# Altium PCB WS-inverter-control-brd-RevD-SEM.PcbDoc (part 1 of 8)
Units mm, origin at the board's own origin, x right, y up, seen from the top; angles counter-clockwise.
Board outline 270 x 105.92 mm, 6 copper layers (Top Layer, Int1 (Sign), Int2 (PWR), Int3 (GND), Int4 (Sign), Bottom Layer), stack 1.509 mm thick; 709 components, 375 nets, 2377 pads, 1332 vias.
Unrouted connection lines stored in the file: 55.
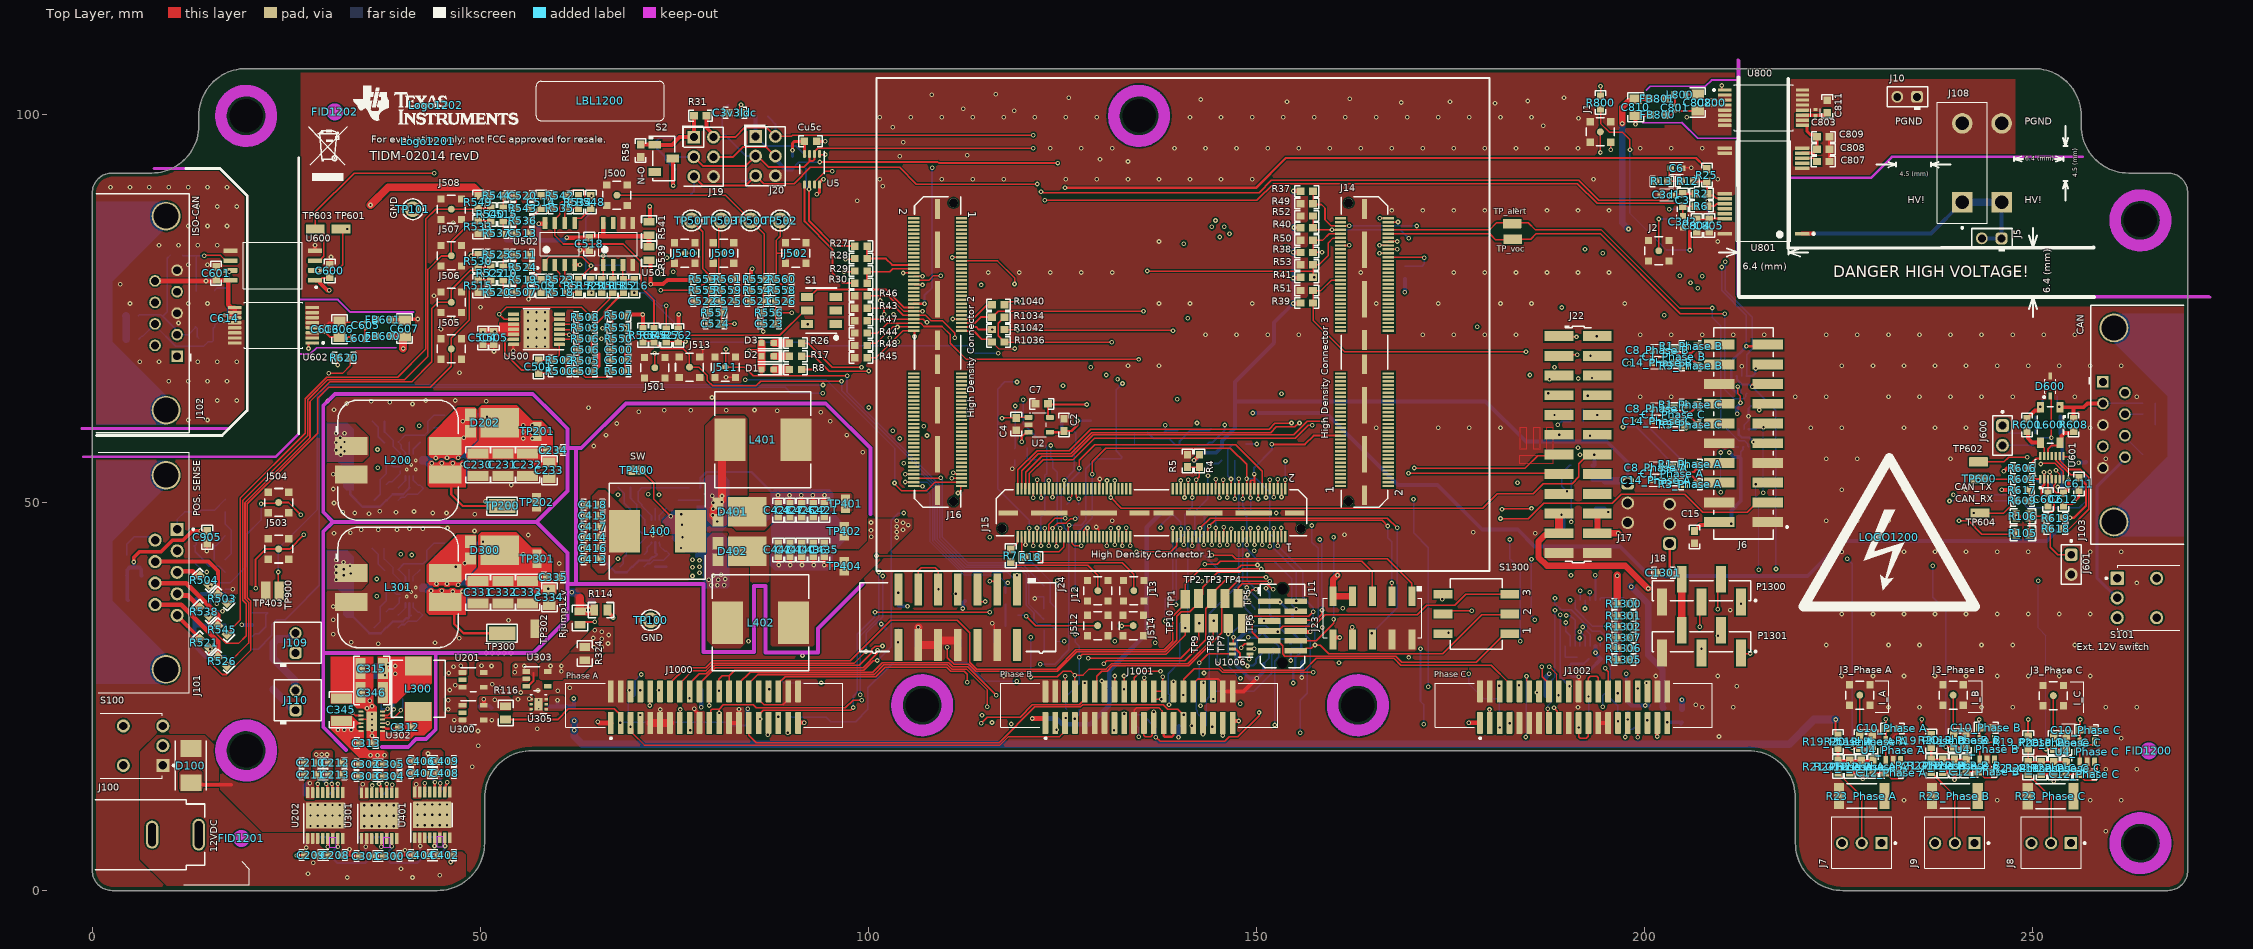
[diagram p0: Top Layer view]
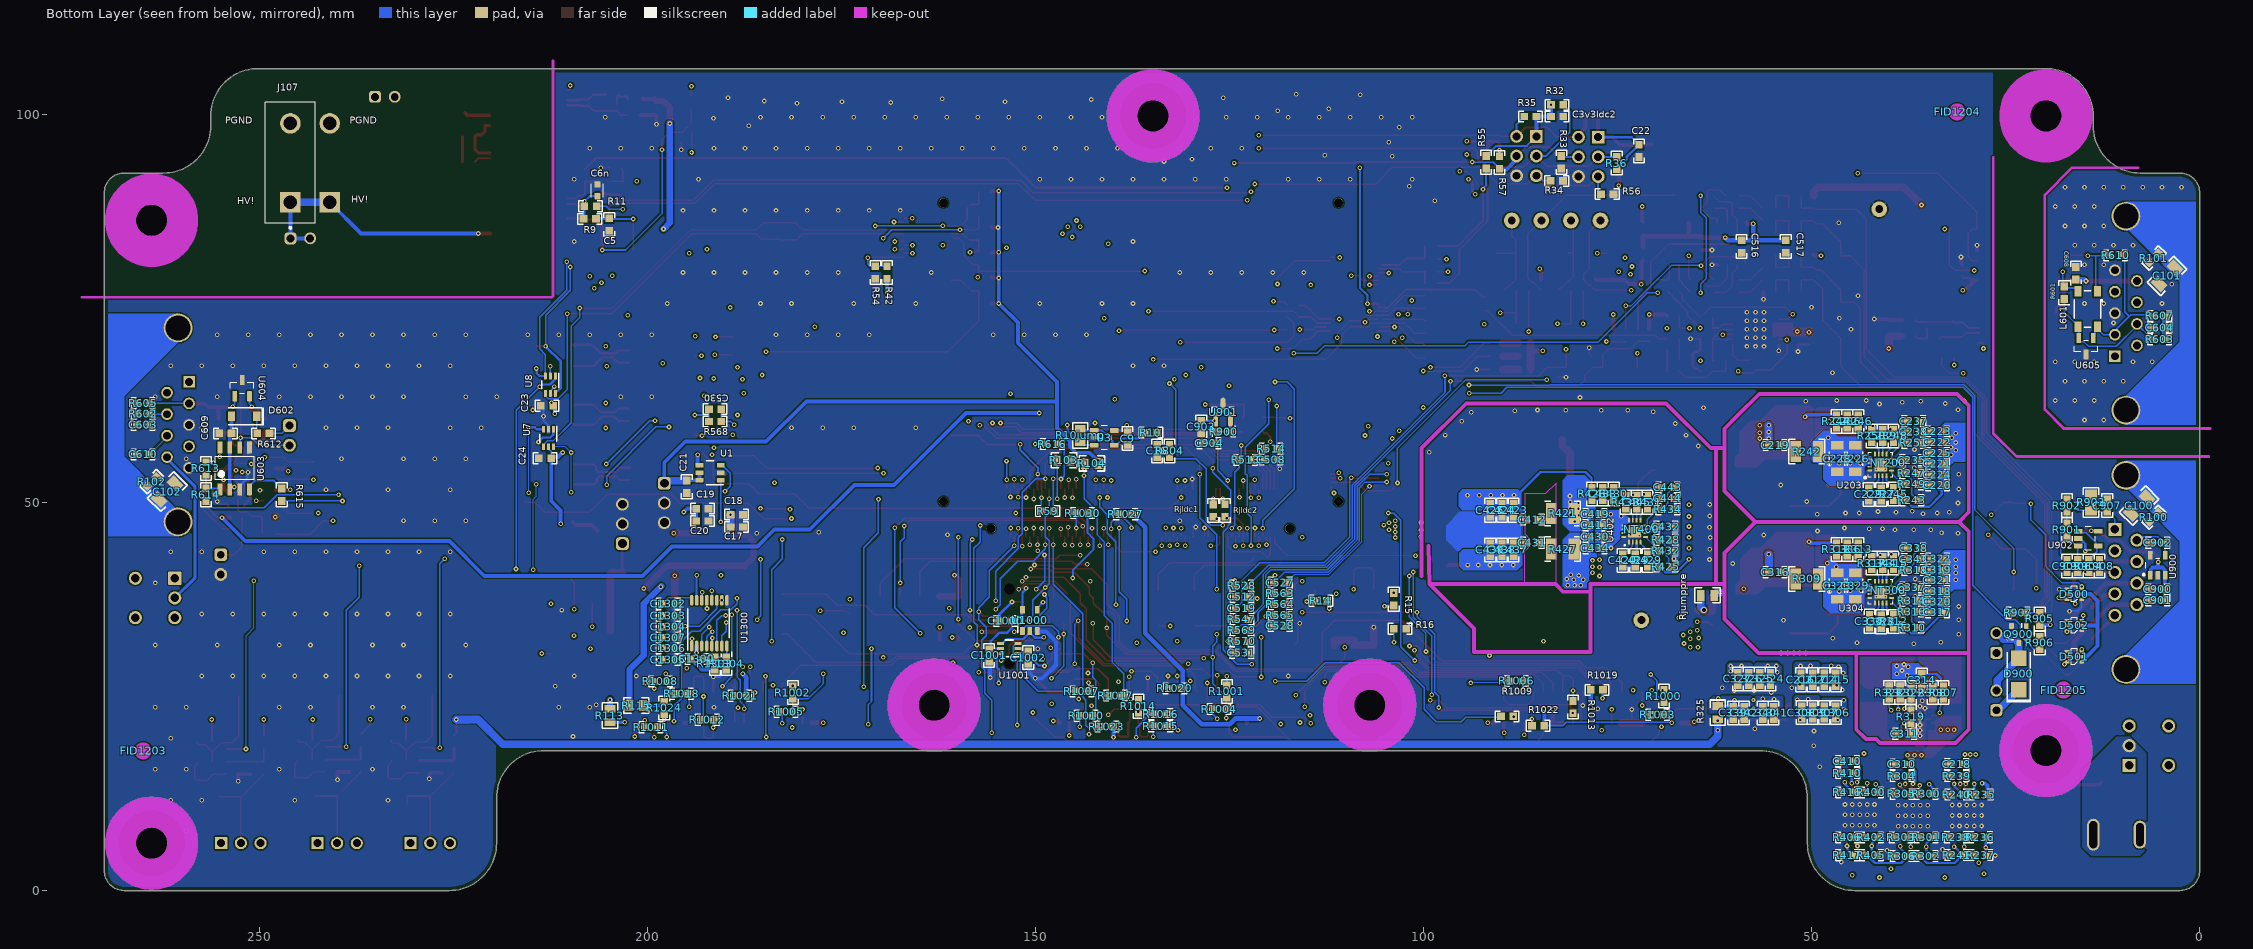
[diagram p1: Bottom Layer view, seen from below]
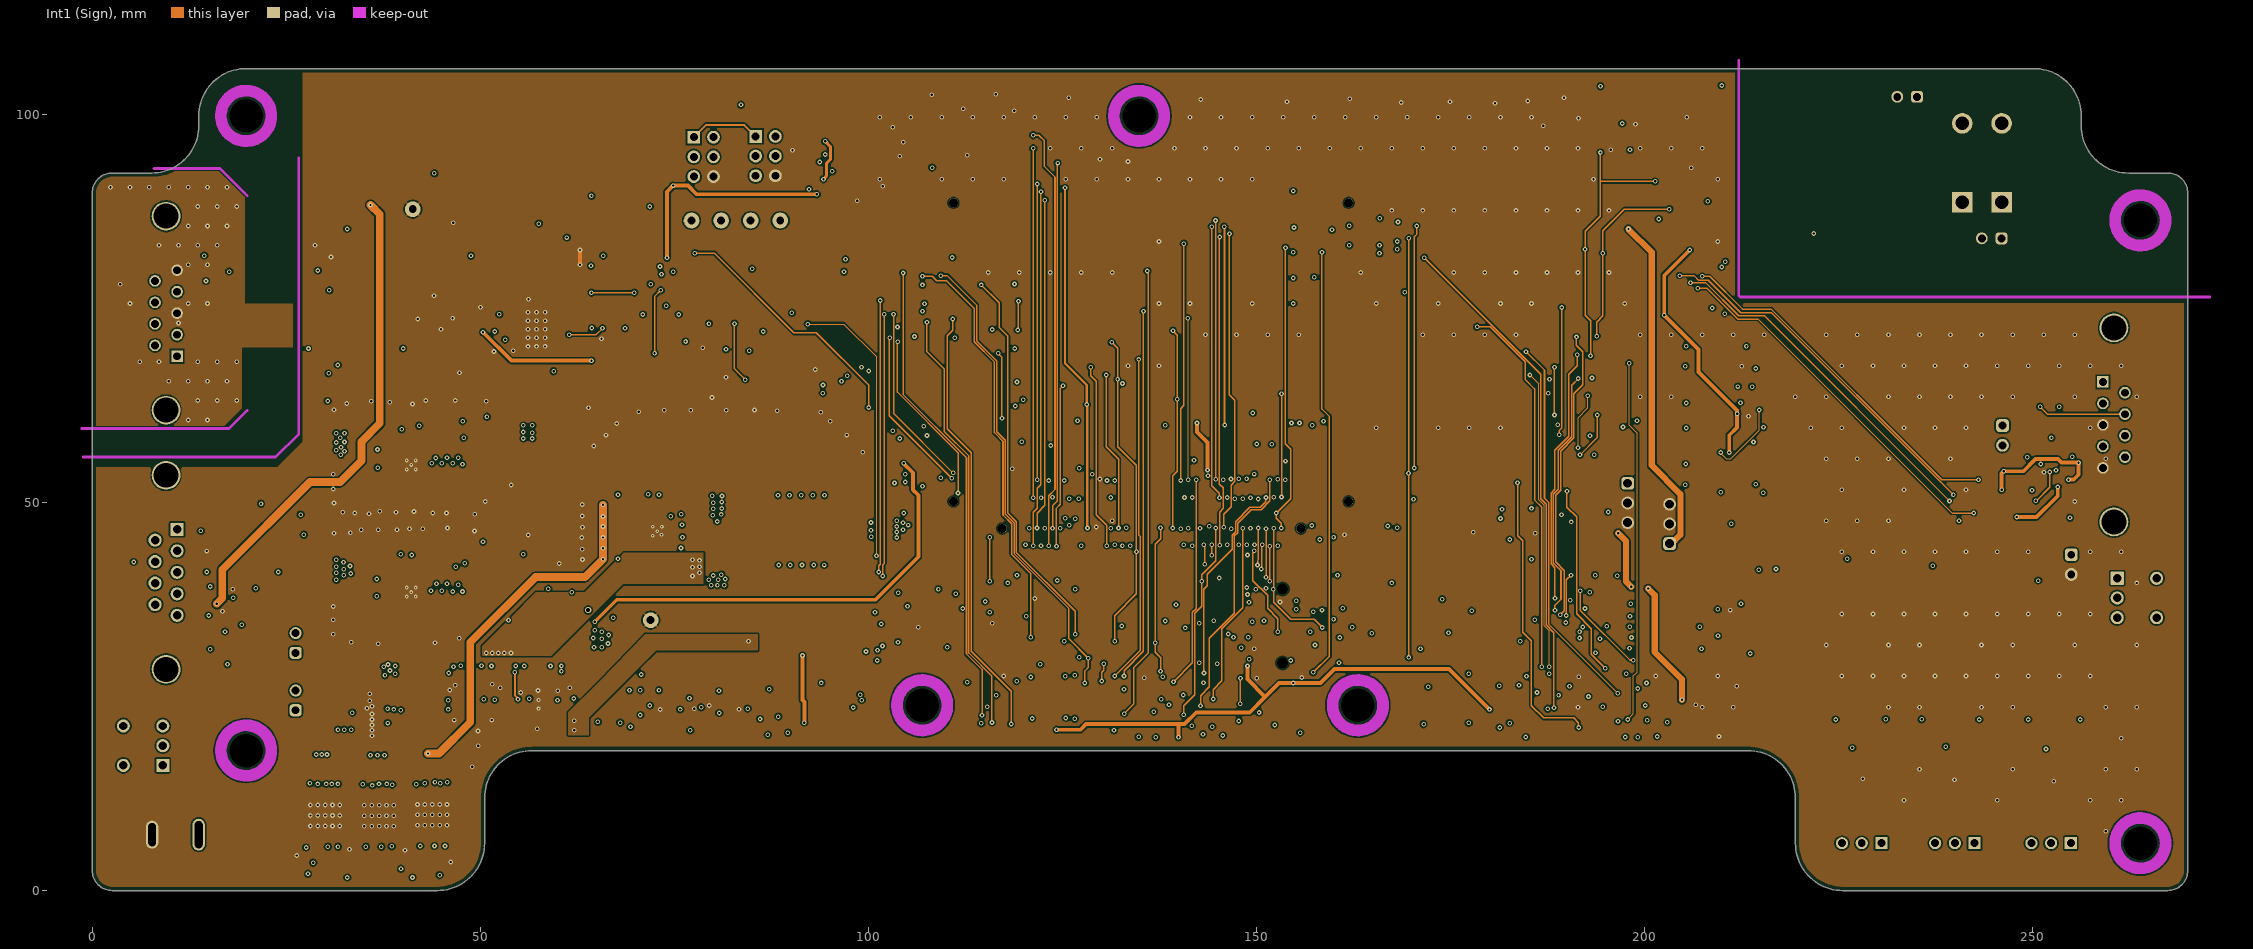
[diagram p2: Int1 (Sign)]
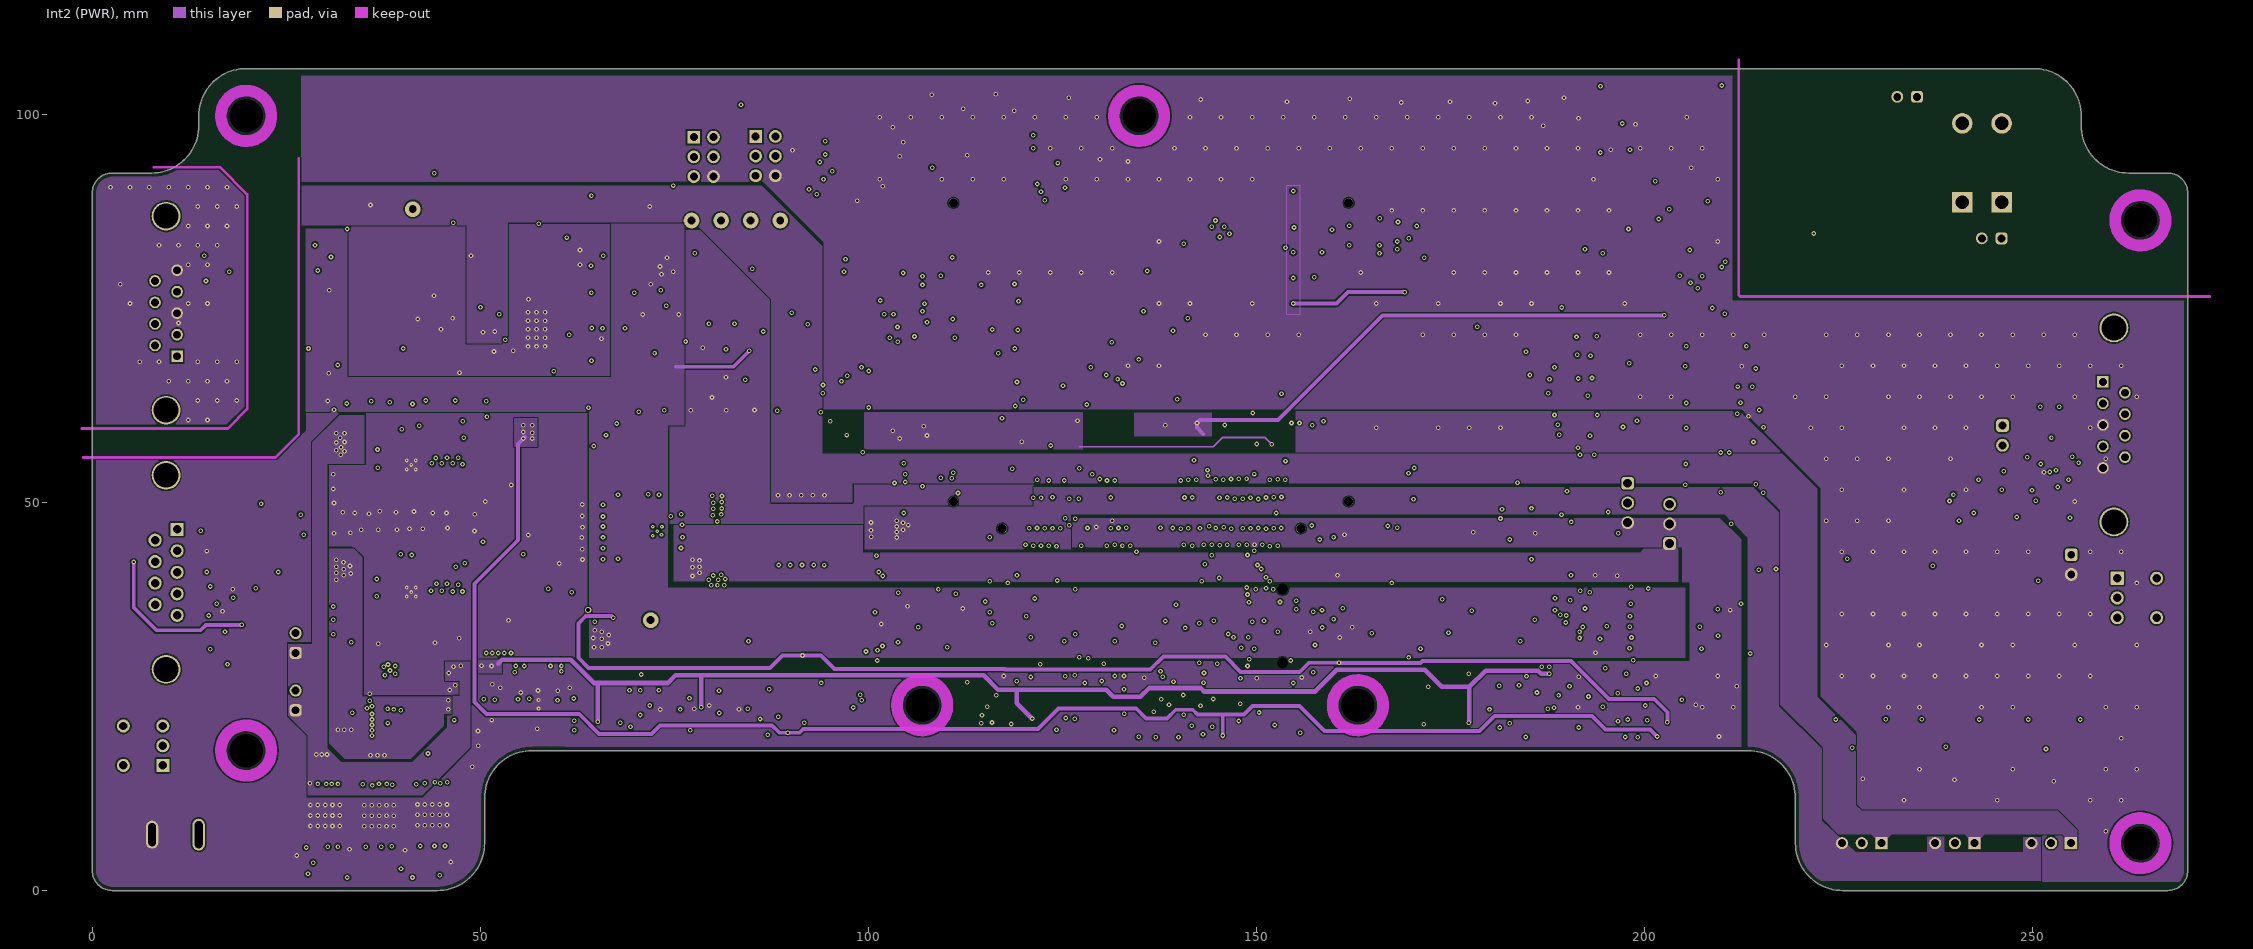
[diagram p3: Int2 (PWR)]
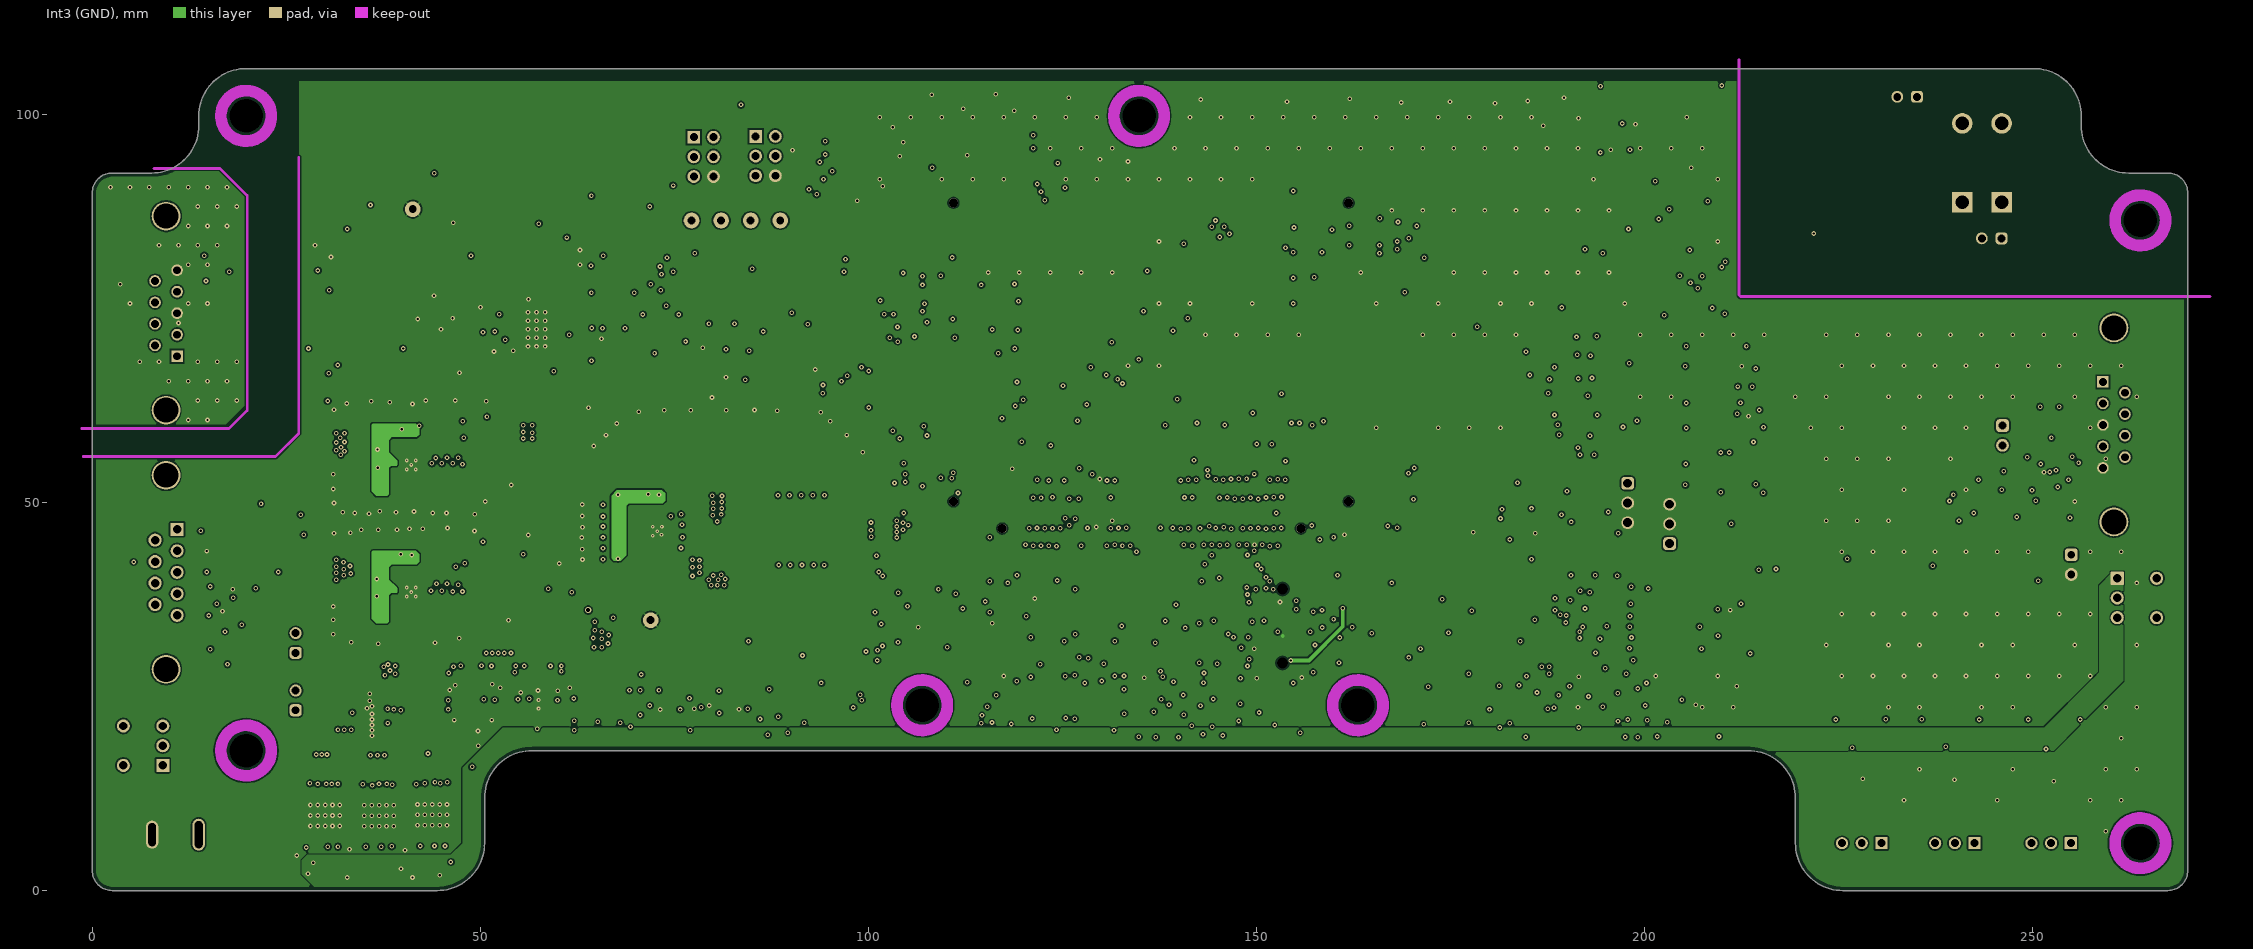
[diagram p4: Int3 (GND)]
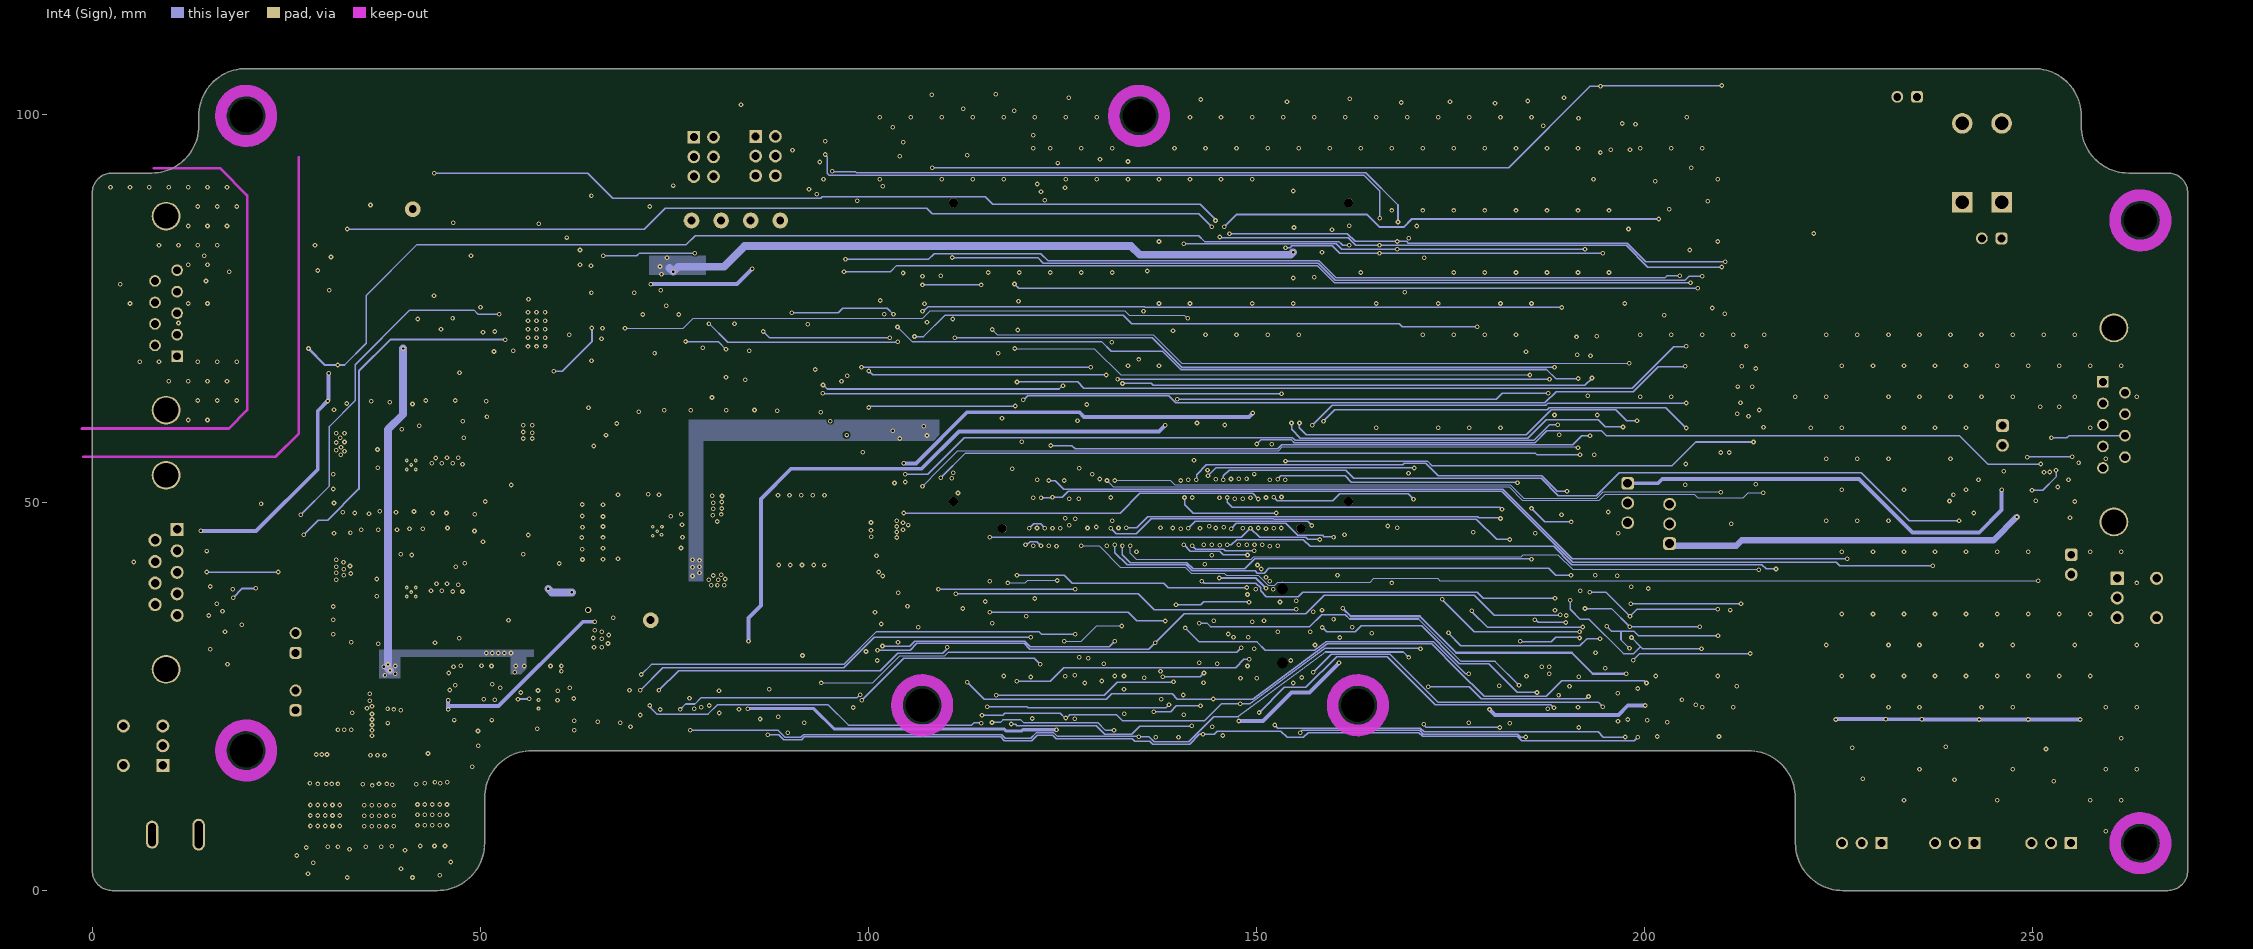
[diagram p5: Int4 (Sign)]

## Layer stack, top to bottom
Top Solder: solder mask 0.0254, SM-001, Dk 4
Top Layer: signal copper 0.035
Dielectric 1: prepreg 0.1118, Composite dielectric, Dk 4.1
Dielectric 2: prepreg 0.0787, Composite dielectric, Dk 4.1
Int1 (Sign): signal copper 0.018
Dielectric 3: core 0.4064, Core-034, Dk 4.6
Int2 (PWR): signal copper 0.018
Dielectric 4: prepreg 0.0864, PP-010, Dk 4
Dielectric 5: prepreg 0.0864, PP-010, Dk 4
Int3 (GND): signal copper 0.018
Dielectric 6: core 0.4064, Core-034, Dk 4.6
Int4 (Sign): signal copper 0.018
Dielectric 7: prepreg 0.0787, Composite dielectric, Dk 4.3
Dielectric 8: prepreg 0.1118, Composite dielectric, Dk 4.3
Bottom Layer: signal copper 0.035
Bottom Solder: solder mask 0.0254, SM-001, Dk 4

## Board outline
2.54,0 44.45,0 ccw(c44.45,6.096) 50.546,6.096 50.546,11.938 cw(c56.642,11.938) 56.642,18.034 213.36,18.034 cw(c213.36,11.938) 219.456,11.938 219.456,6.096 ccw(c225.552,6.096) 225.552,0 267.462,0 ccw(c267.462,2.54) 270.002,2.54 270.002,89.916 ccw(c267.462,89.916) 267.462,92.456 262.382,92.456 cw(c262.382,98.552) 256.286,98.552 256.286,99.822 ccw(c250.19,99.822) 250.19,105.918 19.812,105.918 ccw(c19.812,99.822) 13.716,99.822 13.716,98.552 cw(c7.62,98.552) 7.62,92.456 2.54,92.456 ccw(c2.54,89.916) 0,89.916 0,2.54 ccw(c2.54,2.54)

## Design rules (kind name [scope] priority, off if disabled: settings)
AcuteAngle [All] p1: minimum=4.50000000000000E+0001 checktracksonly=FALSE
AssemblyTestPointUsage [All] p1: valid=2
BoardOutlineClearance BoardOutlineClearance_MountingHoles [(ObjectKind = 'Pad') And (Component = 'Free') And (PadIsPlated = 'False')] p1: gap=0.3 ignorepadtopadclearanceinfootprint=FALSE
BoardOutlineClearance BoardOutlineClearance_Poly [OnCopper and IsPoly] p2: gap=0.5 ignorepadtopadclearanceinfootprint=FALSE
BoardOutlineClearance [OnCopper and Not InComponentClass('Logo') and not InComponentClass('FiducialMark') and not InRegion(1000,500,4000,800) and not InPoly] p3: gap=0.3 ignorepadtopadclearanceinfootprint=FALSE
Clearance Clearance_FiducialMark [IsKeepOut vs (ObjectKind = 'Component') And HasParameterValue('ClassName', 'FiducialMark')] p1: gap=0 ignorepadtopadclearanceinfootprint=FALSE
Clearance Clearance_Keepouts [not HasParameterValue('ClassName', 'FiducialMark') vs IsKeepOut] p2: gap=0.2 ignorepadtopadclearanceinfootprint=FALSE
Clearance Clearance_Mounting_Hole [All vs (ObjectKind = 'Pad') And (Component = 'Free') And (PadIsPlated = 'False')] p3: gap=0.3 ignorepadtopadclearanceinfootprint=FALSE
Clearance Clearance_HV [not InNetClass('HVC') vs InNetClass('HVC')] p4: gap=6 ignorepadtopadclearanceinfootprint=TRUE
Clearance Clearance_Poly [InPolygon] p5: gap=0.2 ignorepadtopadclearanceinfootprint=FALSE
Clearance [All] p6: gap=0.1 ignorepadtopadclearanceinfootprint=FALSE
ComponentClearance ComponentClearance_TestPoints [HasFootprint('Keystone5000') or HasFootprint('Keystone5005') vs HasFootprint('Keystone5000') or HasFootprint('Keystone5005')] p1: gap=0.254 collisioncheckmode=3 verticalgap=0.254 showdistances=FALSE
ComponentClearance ComponentClearance_MountingHoles_FiducialMarks [InComponentClass('Mounting Holes') vs InComponentClass('FiducialMark')] p2: gap=1.27 collisioncheckmode=3 verticalgap=0.254 showdistances=FALSE
ComponentClearance ComponentClearance_Shunt [InComponentClass('Header') vs InComponentClass('Shunt')] p3: gap=0 collisioncheckmode=3 verticalgap=0 showdistances=FALSE
ComponentClearance ComponentClearance_Logo [InComponentClass('Logo')] p4: gap=1.27 collisioncheckmode=3 verticalgap=0.254 showdistances=FALSE
ComponentClearance ComponentClearance_SmallPassives [HasFootprint('0201*') or HasFootprint('0402*') or HasFootprint('0508') or HasFootprint('0603*') or HasFootprint('0612') or HasFootprint('0805*') or HasFootprint('0815*') or HasFootprint('0830*') or HasFootprint('1206*') or HasFootprint('1210*') or HasFootprint('1808*') or HasFootprint('1812*') or HasFootprint('1825*') or HasFootprint('2010*') or HasFootprint('2220*') or HasFootprint('2225*') or HasFootprint('2512*') or HasFootprint('2728*') or HasFootprint('3518*') vs HasFootprint('0201*') or HasFootprint('0402*') or HasFootprint('0508') or HasFootprint('0603*') or HasFootprint('0612') or HasFootprint('0805*') or HasFootprint('0815*') or HasFootprint('0830*') or HasFootprint('1206*') or HasFootprint('1210*') or HasFootprint('1808*') or HasFootprint('1812*') or HasFootprint('1825*') or HasFootprint('2010*') or HasFootprint('2220*') or HasFootprint('2225*') or HasFootprint('2512*') or HasFootprint('2728*') or HasFootprint('3518*')] p5: gap=0.38 collisioncheckmode=3 verticalgap=0.254 showdistances=FALSE
ComponentClearance ComponentClearance_THtoSMT [IsThruComponent vs IsSMTComponent] p6: gap=1.016 collisioncheckmode=3 verticalgap=0.762 showdistances=FALSE
ComponentClearance ComponentClearance_THtoTH [IsThruComponent vs IsThruComponent] p7: gap=0.762 collisioncheckmode=3 verticalgap=0.762 showdistances=FALSE
ComponentClearance [All] p8: gap=0.762 collisioncheckmode=3 verticalgap=0.254 showdistances=FALSE donotcheckwithout3dbody=TRUE
DiffPairsRouting [All] p1: maxlimit=2.54 minlimit=0.254 mostfreqgap=0.254 toplayer_minwidth=0.18 toplayer_maxwidth=0.381 toplayer_prefwidth=0.18 midlayer1_minwidth=0.18 midlayer1_maxwidth=0.381 midlayer1_prefwidth=0.18 midlayer2_minwidth=0.18 midlayer2_maxwidth=0.381 midlayer2_prefwidth=0.18 midlayer3_minwidth=0.18 midlayer3_maxwidth=0.381 midlayer3_prefwidth=0.18 midlayer4_minwidth=0.18 midlayer4_maxwidth=0.381 midlayer4_prefwidth=0.18 bottomlayer_minwidth=0.18 bottomlayer_maxwidth=0.381 bottomlayer_prefwidth=0.18 maxuncoupledlength=25.4
FabricationTestPointUsage TestPointUsage [All] p1: valid=2 allowmultiple=FALSE
FabricationTestpoint Testpoint [All] p1: side=3 testpointundercomponent=TRUE minsize=1.016 maxsize=2.54 preferedsize=1.524 minholesize=0 maxholesize=1.016 preferedholesize=0.813 testpointgrid=0.025 allowsidetop=TRUE allowsidebottom=TRUE usegrid=TRUE gridtolerance=0
FanoutControl Fanout_LCC [IsLCC] p1: bgadir=Out bgaviamode=Centered fanoutstyle=Auto fanoutdirection=Alternating viagrid=0.025 // Fanout_LCC (Default Rule)
FanoutControl Fanout_BGA [IsBGA] p2: bgadir=Out bgaviamode=Centered fanoutstyle=Auto fanoutdirection=Alternating viagrid=0.025 // Fanout_BGA (Default Rule)
FanoutControl Fanout_Default [All] p4: bgadir=Out bgaviamode=Centered fanoutstyle=Auto fanoutdirection=Alternating viagrid=0.025 // Fanout_Default (Default Rule)
FanoutControl Fanout_Small [(CompPinCount < 5)] p5: bgadir=Out bgaviamode=Centered fanoutstyle=Auto fanoutdirection=OutThenIn viagrid=0.025 // Fanout_Small (Default Rule)
HoleSize [All] p1: absolutevalues=TRUE maxlimit=6.375 minlimit=0.2 maxpercent=80.000 minpercent=20.000
MinimumAnnularRing MinimumAnnularRing_1 [All] p1: minimumring=0.15
MinimumAnnularRing MinimumAnnularRing_ThermalPadVias [IsVia and InAnyComponent] p2: minimumring=0.15
MinimumSolderMaskSliver MinimumSolderMaskSliver_Logo [InComponentClass('Logo') vs InComponentClass('Logo')] p1: minsoldermaskwidth=0.018
MinimumSolderMaskSliver [All] p2: minsoldermaskwidth=0.1
PlaneConnect [All] p1: planeconnectstyle=Relief reliefexpansion=0.254 reliefentries=4 reliefconductorwidth=0.254 reliefairgap=0.254
PolygonConnect Testpoint-GND-thermal [(InComponent('TP100') or InComponent('TP101')) and InNet('GND')] p1: connectstyle=Relief reliefconductorwidth=0.254 reliefentries=4 polygonreliefangle="45 Angle" airgapwidth=0.2
PolygonConnect [All] p2: connectstyle=Direct reliefconductorwidth=0.254 reliefentries=4 polygonreliefangle="90 Angle" airgapwidth=0.2
RoutingVias ThermalPadVias [IsVia and InAnyComponent] p1: holewidth=0.2 width=0.5 viastyle="Through Hole" minholewidth=0.2 minwidth=0.5 maxholewidth=0.33 maxwidth=0.6
RoutingVias [All] p2: holewidth=0.3 width=0.6 viastyle="Through Hole" minholewidth=0.2 minwidth=0.5 maxholewidth=1 maxwidth=1.5
SilkToBoardRegionClearance [Not ((IsComment or IsDesignator) And (Hide <> 'False')) and not InRegion(1000,500,4000,800)] p1:
SilkToSilkClearance SilkToSilkClearance_Pb-FreeLogo [(HasFootprint('Pb-Free_Overlay_Medium') OR HasFootprint('Pb-Free_Overlay_Small')) vs (HasFootprint('Pb-Free_Overlay_Medium') OR HasFootprint('Pb-Free_Overlay_Small'))] p1: silktosilkclearance=0
SilkToSilkClearance [All] p2: silktosilkclearance=0.102
SilkToSolderMaskClearance SilkToComponentPadClearance [(IsPad or IsFill or IsRegion) and InAnycomponent] p1: minsilkscreentomaskgap=0.1 clearancetoexposedcopper=TRUE
SilkToSolderMaskClearance "Silk to Solder Mask Opening" [All] p2: minsilkscreentomaskgap=0.102 clearancetoexposedcopper=FALSE
SolderMaskExpansion [All] p1: expansion=0.05 istentingtop=FALSE
UnRoutedNet [All] p1: checkbadconnections=TRUE
Width [not InPolygon] p1: maxlimit=2.54 minlimit=0.16 preferedwidth=0.18 minimp=50.000000 maximp=50.000000 favimp=50.000000 checkconnectedcopper=TRUE
14 further rules are at their usual default settings.

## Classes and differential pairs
component class "Safety MCU": C17 C18 C19 C20 C21 J5 J10 J22 U1
component class LDC5073: C3v3ldc C3v3ldc2 C22 Cu5c J19 J20 R31 R32 R33 R34 R35 R36 R55 R56 R57 R58 S2 U5
component class controlSOM_Subsystem: C2 C4 C7 D1 D2 D3 J11 J12 J13 J14 J15 J16 J17 J18 J23 J24 R7 R8 R14 R15 R16 R17 R18 R26 R27 R28 R29 R30 R59 Rjldc1 Rjldc2 S1 TP1 TP2 TP3 TP4 TP5 TP6 TP7 TP8 TP9 TP10 U2
channel class current-sense-lem-new: "Phase A" "Phase B" "Phase C"
component class U_Voltage-sense-LVside: C3 C3d1 C3d2 C5 C6 C6n C9 C16 J1 J2 R2 R6 R9 R10 R10jump R11 R12 R13 R25 U3
component class "U_Current Sense Connector": C15 C23 C24 J6 J7 J8 J9 TP_alert TP_voc U7 U8
component class "Safe State Behavior Settings": R4 R5 R37 R38 R39 R40 R41 R42 R43 R44 R45 R46 R47 R48 R49 R50 R51 R52 R53 R54
component class "Phase C": "C1_Phase C" "C8_Phase C" "C10_Phase C" "C11_Phase C" "C12_Phase C" "C13_Phase C" "C14_Phase C" "J3_Phase C" "R1_Phase C" "R3_Phase C" "R19_Phase C" "R20_Phase C" "R21_Phase C" "R22_Phase C" "R23_Phase C" "R24_Phase C" "U4_Phase C"
component class "Phase B": "C1_Phase B" "C8_Phase B" "C10_Phase B" "C11_Phase B" "C12_Phase B" "C13_Phase B" "C14_Phase B" "J3_Phase B" "R1_Phase B" "R3_Phase B" "R19_Phase B" "R20_Phase B" "R21_Phase B" "R22_Phase B" "R23_Phase B" "R24_Phase B" "U4_Phase B"
component class "Phase A": "C1_Phase A" "C8_Phase A" "C10_Phase A" "C11_Phase A" "C12_Phase A" "C13_Phase A" "C14_Phase A" "J3_Phase A" "R1_Phase A" "R3_Phase A" "R19_Phase A" "R20_Phase A" "R21_Phase A" "R22_Phase A" "R23_Phase A" "R24_Phase A" "U4_Phase A"
component class Designator: C1300 C1301 C1302 C1303 C1304 C1305 C1306 C1307 P1300 P1301 R1300 R1301 R1302 R1303 R1304 R1305 R1306 R1307 S1300 U1300
net class HVC: 5V_iso_AMC_9 ADJ_NC_9 HV Pgndin_1 VSNS_9
differential pair IFB_W_1: +IFB_W_1_P -IFB_W_1_N
differential pair IFB_V_1: +IFB_V_1_P -IFB_V_1_N
differential pair IFB_U_1: +IFB_U_1_P -IFB_U_1_N
differential pair V_1: +V_1_P -V_1_N
differential pair U_1: +U_1_P -U_1_N
differential pair VOUT_C: +VOUT_C_P -VOUT_C_N
differential pair VDC: +VDC_P -VDC_N

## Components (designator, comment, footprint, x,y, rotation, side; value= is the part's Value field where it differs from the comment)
"C1_Phase A" "06031C102KAT2A" 0603#1 203.573,53.699 r270 top value=1000pF (schematic designator C1)
"C1_Phase B" "06031C102KAT2A" 0603#1 203.814,68.792 r270 top value=1000pF (schematic designator C1)
"C1_Phase C" "06031C102KAT2A" 0603#1 203.773,61.299 r270 top value=1000pF (schematic designator C1)
C2 "CGA3E2X7R1H104K080AA" 0603#1 125.205,60.002 r90 top value=0.1uF
C3 "06035A251JAT2A" 0603#1 204.95,88.978 r270 top value=0.00025uF
C3d1 "06035C100KAT2A" FP-06035C100KAT2A_0603-MFG 202.843,89.636 r0 top value=10pF
C3d2 "06035C100KAT2A" FP-06035C100KAT2A_0603-MFG 204.95,86.178 r90 top value=10pF
C3v3ldc "CGA3E2X7R1H104K080AA" 0603#1 82.793,100.211 r180 top value=0.1uF
C3v3ldc2 "CGA3E2X7R1H104K080AA" 0603#1 82.793,99.736 r180 bottom value=0.1uF
C4 "CGA3E2X7R1H104K080AA" 0603#1 119.043,60.103 r270 top value=0.1uF
C5 "GCM1885C2A221JA16D" 0603#1 204.95,85.828 r270 bottom value=220pF
C6 "06035C100KAT2A" FP-06035C100KAT2A_0603-MFG 204.15,93.078 r180 top value=10pF
C6n "06035C100KAT2A" FP-06035C100KAT2A_0603-MFG 206.469,90.224 r270 bottom value=10pF
C7 "CGA3E2X7R1H104K080AA" 0603#1 122.343,62.703 r180 top value=0.1uF
"C8_Phase A" "06035C100KAT2A" FP-06035C100KAT2A_0603-MFG 201.514,54.492 r0 top value=10pF (schematic designator C8)
"C8_Phase B" "06035C100KAT2A" FP-06035C100KAT2A_0603-MFG 201.714,69.592 r0 top value=10pF (schematic designator C8)
"C8_Phase C" "06035C100KAT2A" FP-06035C100KAT2A_0603-MFG 201.714,62.092 r0 top value=10pF (schematic designator C8)
C9 "CGA3E2X7R1H104K080AA" 0603#1 138.143,58.236 r270 bottom value=0.1uF
"C10_Phase A" "CGA3E2X7R1H104K080AA" 0603#1 231.95,20.878 r0 top value=0.1uF (schematic designator C10)
"C10_Phase B" "CGA3E2X7R1H104K080AA" 0603#1 244.05,20.978 r0 top value=0.1uF (schematic designator C10)
"C10_Phase C" "CGA3E2X7R1H104K080AA" 0603#1 256.95,20.678 r0 top value=0.1uF (schematic designator C10)
"C11_Phase A" "GCM188R72A472KA37D" 0603#1 227.95,15.978 r270 top value=4700pF (schematic designator C11)
"C11_Phase B" "GCM188R72A472KA37D" 0603#1 239.95,16.078 r270 top value=4700pF (schematic designator C11)
"C11_Phase C" "GCM188R72A472KA37D" 0603#1 252.75,15.778 r270 top value=4700pF (schematic designator C11)
"C12_Phase A" "CGA3E2NP01H101J080AA" 0603#1 231.85,15.178 r0 top value=100pF (schematic designator C12)
"C12_Phase B" "CGA3E2NP01H101J080AA" 0603#1 243.85,15.278 r0 top value=100pF (schematic designator C12)
"C12_Phase C" "CGA3E2NP01H101J080AA" 0603#1 256.75,14.978 r0 top value=100pF (schematic designator C12)
"C13_Phase A" "CGA3E2NP01H101J080AA" 0603#1 229.35,19.178 r90 top value=100pF (schematic designator C13)
"C13_Phase B" "CGA3E2NP01H101J080AA" 0603#1 241.443,19.336 r90 top value=100pF (schematic designator C13)
"C13_Phase C" "CGA3E2NP01H101J080AA" 0603#1 254.343,19.036 r90 top value=100pF (schematic designator C13)
"C14_Phase A" "06035C100KAT2A" FP-06035C100KAT2A_0603-MFG 201.514,52.892 r0 top value=10pF (schematic designator C14)
"C14_Phase B" "06035C100KAT2A" FP-06035C100KAT2A_0603-MFG 201.714,67.992 r0 top value=10pF (schematic designator C14)
"C14_Phase C" "06035C100KAT2A" FP-06035C100KAT2A_0603-MFG 201.714,60.492 r0 top value=10pF (schematic designator C14)
C15 "CGA3E2X7R1H104K080AA" 0603#1 206.443,45.536 r270 top value=0.1uF
C16 "CGA3E2NP01H101J080AA" 0603#1 134.343,56.636 r270 bottom value=100pF
C17 "CGA3E2X7R1H104K080AA" 0603#1 188.518,46.836 r180 bottom value=0.1uF
C18 "CGA3E2X7R1H104K080AA" 0603#1 188.518,48.436 r180 bottom value=0.1uF
C19 "CGA3E2X7R1H104K080AA" 0603#1 192.937,49.214 r180 bottom value=0.1uF
C20 "CGA3E2X7R1H104K080AA" 0603#1 192.937,47.614 r180 bottom value=0.1uF
C21 "CGA3E2X7R1H104K080AA" 0603#1 194.943,52.036 r270 bottom value=0.1uF
C22 "CGA3E2X7R1H104K080AA" 0603#1 72.243,95.311 r270 bottom value=0.1uF
C23 "CGA3E2X7R1H104K080AA" 0603#1 212.952,62.477 r0 bottom value=0.1uF
C24 "CGA3E2X7R1H104K080AA" 0603#1 213.214,55.692 r0 bottom value=0.1uF
C100 "12061C103JAT2A" 1206 7.8,49.6 r315 bottom value=0.01uF
C101 "12061C103JAT2A" 1206 4.2,79.2 r315 bottom value=0.01uF
C102 "12061C103JAT2A" 1206 261.9,51.4 r135 bottom value=0.01uF
C208 "GRM188R6YA106MA73D" 0603#2 31.325,4.563 r0 top value=10uF
C209 "CGA3E2X7R1H104K080AA" 0603#2 28.2,4.563 r180 top value=0.1uF
C210 "CGA3E2X7R1H104K080AA" 0603#2 28.175,16.438 r180 top value=0.1uF
C211 "GRM188R6YA106MA73D" 0603#2 28.175,14.938 r180 top value=10uF
C212 "GRM188R6YA106MA73D" 0603#2 31.275,16.438 r0 top value=10uF
C213 "GRM188R6YA106MA73D" 0603#2 31.275,14.938 r0 top value=10uF
C214 "GRM188R6YA106MA73D" 0603#2 48.375,27.15 r270 bottom value=10uF
C215 "CGA3E2X7R1H104K080AA" 0603#2 46.875,27.15 r270 bottom value=0.1uF
C216 "CGA3E2X7R1H104K080AA" 0603#2 51.375,27.15 r270 bottom value=0.1uF
C217 "GRM188R6YA106MA73D" 0603#2 49.875,27.15 r270 bottom value=10uF
C218 "CGA3E2X7R2A103K080AA" 0603#2 31.3,16.263 r0 bottom value=0.01uF
C219 "C0603C681J5GACTU" 0603#2 54.7,57.4 r180 bottom value=680pF
C220 "GRM1885C1H102JA01D" 0603#2 33.8,52.225 r0 bottom value=1000pF
C221 "CGA3E2X7R2A103K080AA" 0603#2 33.8,54.975 r0 bottom value=0.01uF
C222 "CGA3E2X7R1H104K080AA" 0603#2 33.8,57.75 r0 bottom value=0.1uF
C223 "GRM188R6YA106MA73D" 0603#2 33.8,59.15 r0 bottom value=10uF
C224 "GRM188R6YA106MA73D" 0603#2 33.8,53.6 r0 bottom value=10uF
C225 "GRM188R6YA106MA73D" 0603#2 33.8,56.35 r0 bottom value=10uF
C226 "CGA5L1X7R1H106K160AC" 1206_190 44.4,55.65 r270 bottom value=10uF
C227 "CGA3E2X7R2A103K080AA" 0603#2 41.043,51.036 r270 bottom value=0.01uF
C228 "CGA5L1X7R1H106K160AC" 1206_190 46.7,55.65 r270 bottom value=10uF
C229 "CGA3E1X7R1V105K080AC" 0603#2 42.643,51.036 r90 bottom value=1uF
C230 "GRM32ER71H106KA12L" 1210_270#1 49.7,54.85 r270 top value=10uF
C231 "GRM32ER71H106KA12L" 1210_270#1 52.9,54.85 r270 top value=10uF
C232 "GRM32ER71H106KA12L" 1210_270#1 56.1,54.85 r270 top value=10uF
C233 "CGA4J3X7R1H105K125AB" 0805_HV#1 58.9,54.175 r270 top value=1uF
C234 "CGA3E2X7R1H104K080AA" 0603#2 59.4,56.75 r0 top value=0.1uF
C235 "CGA3E2NP01H101J080AA" 0603#2 37.1,55.45 r180 bottom value=100pF
C236 "CGA3E2X7R1H683K080AA" 0603#2 45.4,60.45 r90 bottom value=0.068uF
C237 "CGA3E2X7R1H473K080AA" 0603#2 36.843,60.486 r180 bottom value=0.047uF
C238 "GCM1885C2A221JA16D" 0603#2 36.843,59.086 r180 bottom value=220pF
C239 "GCM188R71E224KA55D" 0603#2 40.843,58.586 r90 bottom value=0.22uF
C300 "GRM188R6YA106MA73D" 0603#2 38.368,4.443 r0 top value=10uF
C301 "CGA3E2X7R1H104K080AA" 0603#2 35.268,4.443 r180 top value=0.1uF
C302 "CGA3E2X7R1H104K080AA" 0603#2 35.257,16.243 r180 top value=0.1uF
C303 "GRM188R6YA106MA73D" 0603#2 35.257,14.743 r180 top value=10uF
C304 "GRM188R6YA106MA73D" 0603#2 38.357,14.743 r0 top value=10uF
C305 "GRM188R6YA106MA73D" 0603#2 38.357,16.243 r0 top value=10uF
C306 "GRM188R6YA106MA73D" 0603#2 46.875,22.925 r270 bottom value=10uF
C307 "CGA3E2X7R1H104K080AA" 0603#2 48.375,22.925 r270 bottom value=0.1uF
C308 "CGA3E2X7R1H104K080AA" 0603#2 51.275,22.925 r270 bottom value=0.1uF
C309 "GRM188R6YA106MA73D" 0603#2 49.875,22.925 r270 bottom value=10uF
C310 "CGA3E2X7R2A103K080AA" 0603#2 38.357,16.243 r0 bottom value=0.01uF
C311 "CGA3E1X7R1V105K080AC" 0603#2 38,20.2 r0 bottom value=1uF
C312 "GCM188R71E224KA55D" 0603#2 40.3,21.05 r0 top value=0.22uF
C313 "CGA3E2X7R1H104K080AA" 0603#2 35.3,19 r0 top value=0.1uF
C314 "CGA3E2X7R1H104K080AA" 0603#2 35.8,27.1 r270 bottom value=0.1uF
C315 "GRM32ER71A226ME20L" 1210_270#2 36,28.6 r180 top value=22uF
C316 "C0603C681J5GACTU" 0603#2 54.7,41 r180 bottom value=680pF
C317 "GRM1885C1H102JA01D" 0603#2 33.8,35.825 r0 bottom value=1000pF
C318 "CGA3E2X7R2A103K080AA" 0603#2 33.8,38.575 r0 bottom value=0.01uF
C319 "CGA3E2X7R1H104K080AA" 0603#2 33.8,41.35 r0 bottom value=0.1uF
C320 "GRM188R6YA106MA73D" 0603#2 33.8,37.2 r0 bottom value=10uF
C321 "GRM188R6YA106MA73D" 0603#2 33.8,39.95 r0 bottom value=10uF
C322 "GRM188R6YA106MA73D" 0603#2 33.8,42.75 r180 bottom value=10uF
C323 "CGA5L1X7R1H106K160AC" 1206_190 46.7,39.25 r270 bottom value=10uF
C324 "CGA3E1X7R1V105K080AC" 0603#2 55.3,27.275 r270 bottom value=1uF
C325 "CGA3E2X7R1H104K080AA" 0603#2 56.7,27.275 r270 bottom value=0.1uF
C326 "CGA3E2X7R1H104K080AA" 0603#2 58.1,27.275 r270 bottom value=0.1uF
C327 "GRM188R6YA106MA73D" 0603#2 59.5,27.275 r270 bottom value=10uF
C328 "CGA3E2X7R2A103K080AA" 0603#2 41.043,34.636 r270 bottom value=0.01uF
C329 "CGA5L1X7R1H106K160AC" 1206_190 44.4,39.25 r270 bottom value=10uF
C330 "CGA3E1X7R1V105K080AC" 0603#2 42.546,34.692 r90 bottom value=1uF
C331 "GRM32ER71H106KA12L" 1210_270#1 49.7,38.45 r270 top value=10uF
C332 "GRM32ER71H106KA12L" 1210_270#1 52.9,38.45 r270 top value=10uF
C333 "GRM32ER71H106KA12L" 1210_270#1 56.1,38.45 r270 top value=10uF
C334 "CGA4J3X7R1H105K125AB" 0805_HV#1 58.9,37.775 r270 top value=1uF
C335 "CGA3E2X7R1H104K080AA" 0603#2 59.4,40.35 r0 top value=0.1uF
C336 "CGA3E2X7R1H683K080AA" 0603#2 45.4,43.95 r90 bottom value=0.068uF
C337 "CGA3E2NP01H101J080AA" 0603#2 37.1,39.05 r180 bottom value=100pF
C338 "CGA3E2X7R1H473K080AA" 0603#2 36.843,44.086 r180 bottom value=0.047uF
C339 "GRM188R6YA106MA73D" 0603#2 60.1,22.875 r270 bottom value=10uF
C340 "CGA3E1X7R1V105K080AC" 0603#2 56.3,22.875 r270 bottom value=1uF
C341 "CGA3E2X7R1H104K080AA" 0603#2 54.9,22.875 r270 bottom value=0.1uF
C342 "CGA3E2X7R1H104K080AA" 0603#2 58.7,22.875 r270 bottom value=0.1uF
C343 "GCM1885C2A221JA16D" 0603#2 36.843,42.686 r180 bottom value=220pF
C344 "GCM188R71E224KA55D" 0603#2 40.843,42.186 r90 bottom value=0.22uF
C345 "GRM32ER71H106KA12L" 1210_270#2 32.1,23.3 r90 top value=10uF
C346 "GRM32ER71A226ME20L" 1210_270#2 36,25.5 r180 top value=22uF
C402 "GRM188R6YA106MA73D" 0603#2 45.4,4.543 r0 top value=10uF
C404 "CGA3E2X7R1H104K080AA" 0603#2 42.3,4.543 r180 top value=0.1uF
C406 "CGA3E2X7R1H104K080AA" 0603#2 42.3,16.643 r180 top value=0.1uF
C407 "GRM188R6YA106MA73D" 0603#2 42.3,15.143 r180 top value=10uF
C408 "GRM188R6YA106MA73D" 0603#2 45.4,15.143 r0 top value=10uF
C409 "GRM188R6YA106MA73D" 0603#2 45.4,16.643 r0 top value=10uF
C410 "CGA3E2X7R2A103K080AA" 0603#2 45.4,16.643 r0 bottom value=0.01uF
C411 "GRM188R6YA106MA73D" 0603#2 77.9,47.05 r0 bottom value=10uF
C412 "C0603C681J5GACTU" 0603#2 86,47.8 r180 bottom value=680pF
C413 "GRM1885C1H102JA01D" 0603#2 64.5,42.7 r180 top value=1000pF
C414 "CGA3E2X7R2A103K080AA" 0603#2 64.5,45.5 r180 top value=0.01uF
C415 "CGA3E2X7R1H104K080AA" 0603#2 64.5,48.3 r180 top value=0.1uF
C416 "GRM188R6YA106MA73D" 0603#2 64.5,44.1 r180 top value=10uF
C417 "GRM188R6YA106MA73D" 0603#2 64.5,46.9 r180 top value=10uF
C418 "GRM188R6YA106MA73D" 0603#2 64.5,49.7 r180 top value=10uF
C419 "GRM188R6YA106MA73D" 0603#2 77.9,48.5 r0 bottom value=10uF
C420 "CGA3E1X7R1V105K080AC" 0603#2 74.343,42.536 r90 bottom value=1uF
C421 "CGA3E2X7R1H104K080AA" 0603#2 94.3,49 r270 top value=0.1uF
C422 "CGA3E1X7R1V105K080AC" 0603#2 92.9,49 r270 top value=1uF
C423 "GRM188R6YA106MA73D" 0603#2 88.4,49 r90 bottom value=10uF
C424 "GRM188R6YA106MA73D" 0603#2 89.9,49 r90 bottom value=10uF
C425 "GRM188R6YA106MA73D" 0603#2 91.4,49 r90 bottom value=10uF
C426 "GRM188R6YA106MA73D" 0603#2 91.4,49 r90 top value=10uF
C427 "GRM188R6YA106MA73D" 0603#2 89.9,49 r90 top value=10uF
C428 "GRM188R6YA106MA73D" 0603#2 88.4,49 r90 top value=10uF
C429 "CGA3E2X7R2A103K080AA" 0603#2 72.743,42.536 r270 bottom value=0.01uF
C430 "GRM188R6YA106MA73D" 0603#2 77.9,45.6 r0 bottom value=10uF
C431 "C0603C681J5GACTU" 0603#2 86,44.8 r180 bottom value=680pF
C432 "CGA3E2NP01H101J080AA" 0603#2 68.8,46.9 r180 bottom value=100pF
C433 "CGA3E2X7R1H683K080AA" 0603#2 76.9,51.1 r90 bottom value=0.068uF
C434 "GRM188R6YA106MA73D" 0603#2 77.9,44.1 r0 bottom value=10uF
C435 "CGA3E2X7R1H104K080AA" 0603#2 94.3,43.9 r270 top value=0.1uF
C436 "CGA3E1X7R1V105K080AC" 0603#2 92.9,43.9 r270 top value=1uF
C437 "GRM188R6YA106MA73D" 0603#2 88.4,43.9 r90 bottom value=10uF
C438 "GRM188R6YA106MA73D" 0603#2 89.9,43.9 r90 bottom value=10uF
C439 "GRM188R6YA106MA73D" 0603#2 91.4,43.9 r90 bottom value=10uF
C440 "GRM188R6YA106MA73D" 0603#2 91.4,43.9 r90 top value=10uF
C441 "GRM188R6YA106MA73D" 0603#2 89.9,43.9 r90 top value=10uF
C442 "GRM188R6YA106MA73D" 0603#2 88.4,43.9 r90 top value=10uF
C443 "CGA3E2X7R1H473K080AA" 0603#2 68.543,51.936 r180 bottom value=0.047uF
C444 "GCM1885C2A221JA16D" 0603#2 68.543,50.536 r180 bottom value=220pF
C445 "GCM188R71E224KA55D" 0603#2 72.543,50.036 r90 bottom value=0.22uF
C500 "CGA3E2X7R1H683K080AA" 0603#2 67.838,69.711 r0 top value=0.068uF
C501 "GRM1885C1H102JA01D" 0603#2 57.5,67.5 r270 top value=1000pF
C502 "CGA3E2X7R1H104K080AA" 0603#2 67.838,68.311 r180 top value=0.1uF
C503 "CGA3E2X7R2A103K080AA" 0603#2 63.544,66.911 r0 top value=0.01uF
C504 "GRM188R6YA106MA73D" 0603#2 50.338,71.211 r270 top value=10uF
C505 "CGA3E2X7R1H104K080AA" 0603#2 51.738,71.211 r270 top value=0.1uF
C506 "CGA3E2X7R2A103K080AA" 0603#2 63.544,69.686 r180 top value=0.01uF
C507 "GRM1885C1H102JA01D" 0603#2 55.438,77.111 r0 top value=1000pF
C508 "C0603C681J5GACTU" 0603#2 119.643,55.536 r0 bottom value=680pF
C509 "GRM1885C1H102JA01D" 0603#2 57.838,77.911 r270 top value=1000pF
C510 "CGA3E2X7R2A103K080AA" 0603#2 52.938,79.511 r90 top value=0.01uF
C511 "GRM1885C1H102JA01D" 0603#2 55.438,81.911 r180 top value=1000pF
C512 "C0603C681J5GACTU" 0603#2 123.418,37.842 r0 bottom value=680pF
C513 "GRM1885C1H102JA01D" 0603#2 55.438,84.711 r0 top value=1000pF
C514 "GRM1885C1H102JA01D" 0603#2 57.838,88.711 r270 top value=1000pF
C515 "CGA3E2X7R2A103K080AA" 0603#2 52.938,87.111 r90 top value=0.01uF
C516 "GRM188R6YA106MA73D" 0603#2 59.025,82.979 r270 bottom value=10uF
C517 "CGA3E2X7R1H104K080AA" 0603#2 53.325,82.979 r270 bottom value=0.1uF
C518 "CGA3E2X7R1H104K080AA" 0603#2 64.038,83.311 r270 top value=0.1uF
C519 "C0603C681J5GACTU" 0603#2 123.418,36.342 r0 bottom value=680pF
C520 "GRM1885C1H102JA01D" 0603#2 55.438,89.511 r180 top value=1000pF
C521 "C0603C681J5GACTU" 0603#1 85.65,75.953 r180 top value=680pF
C522 "C0603C681J5GACTU" 0603#1 78.65,75.953 r180 top value=680pF
C523 "C0603C681J5GACTU" 0603#1 87.25,73.053 r180 top value=680pF
C524 "C0603C681J5GACTU" 0603#1 80.25,73.053 r180 top value=680pF
C525 "C0603C681J5GACTU" 0603#1 81.85,75.953 r180 top value=680pF
C526 "C0603C681J5GACTU" 0603#1 88.85,75.953 r180 top value=680pF
C527 "C0603C681J5GACTU" 0603#1 118.468,39.686 r180 bottom value=680pF
C528 "C0603C681J5GACTU" 0603#1 118.468,34.086 r180 bottom value=680pF
C530 "C0603C681J5GACTU" 0603#1 191.293,62.036 r0 bottom value=680pF
C531 "C0603C681J5GACTU" 0603#1 123.443,30.636 r180 bottom value=680pF
C600 "CGA3E2X7R1H104K080AA" 0603#2 30.601,79.849 r90 top value=0.1uF
C601 "CGA3E2X7R1H104K080AA" 0603#2 15.943,79.536 r90 top value=0.1uF
C602 "CGA3E2X7R1H104K080AA" 0603#2 252,50.4 r90 top value=0.1uF
C603 "CGA3E2X7R2A472K080AA" 0603#2 265,60.006 r0 bottom value=4700pF
C604 "CGA3E2X7R2A472K080AA" 0603#2 5.143,72.536 r180 bottom value=4700pF
C605 "GCM155R71H153KA55D" FP-GCM155R71H153KA55D_0402-MFG 35.243,72.836 r270 top value=15nF
C606 "GCJ21BR71A106KE01L" 0805_HV#2 31.843,72.336 r90 top value=10uF
C607 "GCJ21BR71A106KE01L" 0805_HV#2 40.234,72.415 r90 top value=10uF
C608 "CL10A226MO7JZNC" 0603#2 15.943,79.536 r90 bottom value=22uF
C609 "CGA3E2X7R1H104K080AA" 0603#2 254.4,58.9 r0 bottom value=0.1uF
C610 "GCM1885C2A221JA16D" 0603#2 265,56.2 r0 bottom value=220pF
C611 "CGA3E2X7R1H104K080AA" 0603#1 256,52.4 r90 top value=0.1uF
C612 "CGA3E2X7R1H104K080AA" 0603#1 254,50.4 r90 top value=0.1uF
C613 "GCM155R71H153KA55D" FP-GCM155R71H153KA55D_0402-MFG 30.043,72.336 r270 top value=15nF
C614 "GCM155R71H153KA55D" FP-GCM155R71H153KA55D_0402-MFG 17.043,73.736 r90 top value=15nF
C800 "GCM155R71H153KA55D" FP-GCM155R71H153KA55D_0402-MFG 208.643,101.536 r270 top value=15nF
C801 "GCM155R71H153KA55D" FP-GCM155R71H153KA55D_0402-MFG 203.943,100.836 r270 top value=15nF
C802 "GCJ21BR71A106KE01L" 0805_HV#2 206.843,101.536 r90 top value=10uF
C803 "GCM155R71H153KA55D" FP-GCM155R71H153KA55D_0402-MFG 222.043,100.236 r90 top value=15nF
C804 "CGA3E1X7R1V105K080AC" 0603#2 206.75,85.678 r270 top value=1uF
C805 "GRM1885C1H102JA01D" 0603#2 208.35,85.678 r270 top value=1000pF
C807 "GRM1885C1H101JA01D" 0603#1 223.043,93.936 r0 top value=100pF
C808 "GRM1885C1H102JA01D" 0603#2 223.053,95.511 r180 top value=1000pF
C809 "CGA3E1X7R1V105K080AC" 0603#2 223.053,97.111 r180 top value=1uF
C810 "GCJ21BR71A106KE01L" 0805_HV#2 198.882,100.94 r90 top value=10uF
C811 "CL10A226MO7JZNC" 0603#2 223.543,101.036 r270 top value=22uF
C900 "GRM188R71A225KE15J" 0603#2 5.4,38.8 r0 bottom value=2.2uF
C901 "CGA3E2X7R1H104K080AA" 0603#2 5.4,37.4 r180 bottom value=0.1uF
C902 "GRM188R71A225KE15J" 0603#2 5.4,44.8 r0 bottom value=2.2uF
C903 "CGA3E2X7R1H104K080AA" 0603#2 128.643,59.736 r270 bottom value=0.1uF
C904 "GRM188R72A681KA01D" 0603#2 127.643,57.636 r0 bottom value=680pF
C905 "CGA3E2X7R1H104K080AA" 0603#2 14.808,45.517 r90 top value=0.1uF
C906 "GCM188R72A472KA37D" 0603#2 15.7,41.8 r270 bottom value=4700pF
C907 "CGA3E2NP01H101J080AA" 0603#2 11.9,49.6 r90 bottom value=100pF
C908 "GCM188R72A472KA37D" 0603#2 12.9,41.8 r270 bottom value=4700pF
C909 "CGA3E2X7R2A103K080AA" 0603#2 17.1,41.8 r270 bottom value=0.01uF
C1000 "GRM1885C1H102JA01D" 0603#1 153.843,34.736 r180 bottom value=1000pF
C1001 "GRM1885C1H102JA01D" 0603#1 155.994,30.288 r90 bottom value=1000pF
C1002 "GRM1885C1H102JA01D" 0603#1 150.949,30.018 r90 bottom value=1000pF
C1300 "CGA3E2X7R1H104K080AA" 0603#2 193.643,29.836 r180 bottom value=0.1uF
C1301 "CGA3E2X7R1H104K080AA" 0603#2 202.443,40.936 r0 top value=0.1uF
C1302 "GRM1885C1H102JA01D" 0603#2 197.343,36.936 r180 bottom value=1000pF
C1303 "GRM1885C1H102JA01D" 0603#2 197.343,35.4 r180 bottom value=1000pF
C1304 "GRM1885C1H102JA01D" 0603#2 197.343,34 r180 bottom value=1000pF
C1305 "GRM1885C1H102JA01D" 0603#2 197.343,29.714 r180 bottom value=1000pF
C1306 "GRM1885C1H102JA01D" 0603#2 197.343,31.2 r180 bottom value=1000pF
C1307 "GRM1885C1H102JA01D" 0603#2 197.343,32.6 r180 bottom value=1000pF
Cu5c "CGA3E2X7R1H104K080AA" 0603#1 92.543,96.536 r180 top value=0.1uF
D1 "150060GS75000" WL-SMCW_GREEN 87.014,67.136 r180 top value=Green
D2 "150060RS75000" WL-SMCW_RED 87.014,68.836 r180 top value=Red
D3 "150060GS75000" WL-SMCW_GREEN 87.014,70.536 r180 top value=Green
D100 "SMBJ28CA-13-F" SMB-Bi 12.7,16.1 r270 top value=28V
D202 "PMEG060V100EPDZ" SOT1289 51.5,60.25 r90 top value=60V
D300 "PMEG060V100EPDZ" SOT1289 51.5,43.85 r90 top value=60V
D401 "PMEG060V100EPDZ" SOT1289 83.4,48.8 r90 top value=60V
D402 "PMEG060V100EPDZ" SOT1289 83.4,43.7 r90 top value=60V
D500 "BAS40DW-04-TP" SOT-363 16.15,38.199 r0 bottom value=40V
D501 "BAS40DW-04-TP" SOT-363 16.15,30.119 r0 bottom value=40V
D502 "BAS40DW-04-TP" SOT-363 16.15,34.159 r0 bottom value=40V
D600 "ESD1LIN24DYFR" DYF0002A-MFG 252.3,65 r90 top
D602 "1N4148W-TP" SOD-123 252,61.1 r0 bottom value=100V
D900 "SS12-E3/61T" SMA 23.3,27.9 r90 bottom value=20V
FB600 "LCMGA160808T601RG" FP-LCMGA160808T601RG_0603-MFG 37.443,71.436 r180 top
FB601 "LCMGA160808T601RG" FP-LCMGA160808T601RG_0603-MFG 37.443,73.536 r180 top
FB800 "LCMGA160808T601RG" FP-LCMGA160808T601RG_0603-MFG 201.743,99.936 r180 top
FB801 "LCMGA160808T601RG" FP-LCMGA160808T601RG_0603-MFG 201.643,102.036 r180 top
FID1200 "Fiducial" Fiducial10-20 265,18 r90 top
FID1201 "Fiducial" Fiducial10-20 19.202,6.706 r90 top
FID1202 "Fiducial" Fiducial10-20 31.243,100.336 r90 top
FID1203 "Fiducial" Fiducial10-20 265,18 r90 bottom
FID1204 "Fiducial" Fiducial10-20 31.243,100.336 r90 bottom
FID1205 "Fiducial" Fiducial10-20 17.543,25.836 r90 bottom
J1 "73415-2063" Molex_73415-2063 194.323,97.756 r90 top
J2 "73415-2063" Molex_73415-2063 201.843,82.436 r0 top
"J3_Phase A" "73415-2063" Molex_73415-2063 227.75,25.178 r90 top (schematic designator J3)
"J3_Phase B" "73415-2063" Molex_73415-2063 239.78,25.178 r90 top (schematic designator J3)
"J3_Phase C" "73415-2063" Molex_73415-2063 252.69,25.111 r90 top (schematic designator J3)
J5 "TSW-102-08-G-S" Samtec_TSW-102-08-x-S 244.743,84.036 r180 top
J6 "IPL1-110-02-L-D-K" FP-IPL1-110-02-L-D-K-0 212.753,58.906 r180 top
J7 "22232031" FP-22232031_HDR3-MFG 228.003,6.178 r180 top
J8 "22232031" FP-22232031_HDR3-MFG 252.403,6.178 r180 top
J9 "22232031" FP-22232031_HDR3-MFG 240.003,6.178 r180 top
J10 "TSW-102-08-G-S" Samtec_TSW-102-08-x-S 233.85,102.278 r180 top
J11 "TFM-106-02-S-D-A" Samtec_TFM-106-02-x-D-A 153.365,34.083 r0 top
J12 "73415-2063" Molex_73415-2063 129.563,38.636 r180 top
J13 "73415-2063" Molex_73415-2063 134.199,38.636 r180 top
J14 "QTH-060-01-L-D-A" SAMTEC_QTH-060-01-L-D-A 163.915,69.372 r90 top locked
J15 "QTH-060-01-L-D-A" SAMTEC_QTH-060-01-L-D-A 136.483,48.671 r180 top locked
J16 "QTH-060-01-L-D-A" SAMTEC_QTH-060-01-L-D-A 108.924,69.372 r270 top locked
J17 "61300311121" WURTH_61300311121 197.843,49.936 r270 top
J18 "61300311121" WURTH_61300311121 203.243,47.236 r90 top
J19 "PEC03DAAN" SULLINS_PEC03DAAN 78.773,94.536 r270 top
J20 "PEC03DAAN" SULLINS_PEC03DAAN 86.743,94.636 r270 top
J22 "TSM-112-01-L-DV" Samtec_TSM-112-01-x-DV 191.468,57.466 r0 top
J23 "TSM-105-01-T-DV-P" CONN_TSM-105-01-T-DV-P 164.943,35.136 r180 top
J24 "SBH11-NBPC-D07-SM-BK" Sullins_SBH11-xxxC-D07-SM-BK 111.513,35.251 r270 top
J100 "PJ-037AH" CUI_PJ-037AH 10.7,7.2 r270 top locked
J101 "618009231221" FP-618009231221_CONN_DSUB_30MM8_18MM4-MFG 3.2,41 r270 top locked
J102 "618009231121" Wurth_618009231121 0,74.4 r180 top locked
J103 "618009231121" Wurth_618009231121 270,60 r0 top locked
J107 "HPM-03-01-T-S" FP-HPM-03-01-T-S_HDR3-MFG 246.032,93.769 r90 bottom locked
J108 "HPM-03-01-T-S" FP-HPM-03-01-T-S_HDR3-MFG 240.952,93.769 r90 top locked
J109 "640456-2" TE_640456-2 26.2,31.9 r90 top
J110 "640456-2" TE_640456-2 26.2,24.5 r90 top
J500 "73415-2063" Molex_73415-2063 67.589,89.589 r0 top
J501 "73415-2063" Molex_73415-2063 72.473,67.363 r0 top
J502 "73415-2063" Molex_73415-2063 90.643,82.136 r0 top
J503 "73415-2063" Molex_73415-2063 24,44 r0 top
J504 "73415-2063" Molex_73415-2063 24,50 r0 top
J505 "73415-2063" Molex_73415-2063 46.254,69.795 r0 top
J506 "73415-2063" Molex_73415-2063 46.254,75.795 r0 top
J507 "73415-2063" Molex_73415-2063 46.254,81.795 r0 top
J508 "73415-2063" Molex_73415-2063 46.254,87.795 r0 top
J509 "73415-2063" Molex_73415-2063 81.343,82.136 r0 top
J510 "73415-2063" Molex_73415-2063 76.343,82.136 r0 top
J511 "73415-2063" Molex_73415-2063 81.543,67.436 r0 top
J512 "73415-2063" Molex_73415-2063 129.543,34.136 r0 top
J513 "73415-2063" Molex_73415-2063 76.943,67.436 r90 top
J514 "73415-2063" Molex_73415-2063 134.127,34.136 r0 top
J600 "TSW-102-07-G-S" TSW-102-07-G-S 246.143,58.636 r270 top
J601 "TSW-102-07-G-S" TSW-102-07-G-S 255,42 r270 top
J1000 "ESHF-120-01-L-D-SM" FP-ESHF-120-01-L-D-SM_HDR40-MFG 78.874,23.876 r0 top locked
J1001 "ESHF-120-01-L-D-SM" FP-ESHF-120-01-L-D-SM_HDR40-MFG 134.874,23.876 r0 top locked
J1002 "ESHF-120-01-L-D-SM" FP-ESHF-120-01-L-D-SM_HDR40-MFG 190.874,23.876 r0 top locked
L200 "MSD1514-473MEB" MSD1514 39.4,55.45 r0 top value=47uH
L300 "IHLP2525CZER2R2M5A" IHLP-2525CZ-5A 42,26 r90 top value=2.2uH
L301 "MSD1514-473MEB" MSD1514 39.4,39.05 r0 top value=47uH
L400 "MSS1278T-103MLB" MSS1278T 72.8,46.3 r0 top value=10uH
L401 "MSS1278T-223MLB" MSS1278T 86.4,58.1 r180 top value=22uH
L402 "MSS1278T-223MLB" MSS1278T 86.1,34.5 r0 top value=22uH
L600 "ACT45B-101-2P-TL003" ACT45B 252.3,60 r270 top value=100uH
L601 "ACT45B-101-2P-TL003" ACT45B 14.443,74.936 r270 bottom value=100uH
L602 "74479763222" WE-PMI_0603_L1.6W0.8H0.8 34.343,71.136 r180 top
L800 "74479763222" WE-PMI_0603_L1.6W0.8H0.8 204.543,102.536 r180 top
LBL1200 "THT-14-423-10" Label_650x200 65.443,101.736 r0 top
LOGO1200 "DANGER HIGH VOLTAGE" IEC_HighVoltage_Large 231.543,45.536 r0 top
Logo1201 "FCC disclaimer" FCC_disclaimer 43.25,96.578 r0 top
Logo1202 "Texas Instruments" TI_Stacked_Overlay_Small 44.247,101.194 r0 top
Logo1203 "WEEE logo" WEEE_Minimum 30.333,95.833 r0 top
NT200 "Net-Tie" Net-Tie_10mil 40.154,55.1 r180 bottom net-tie
NT300 "Net-Tie" Net-Tie_10mil 40.1,38.7 r180 bottom net-tie
NT400 "Net-Tie" Net-Tie_10mil 71.9,46.55 r180 bottom net-tie
P1300 "TSM-105-01-T-SV" SMTC-TSM-105-01-X-SV 207.343,38.636 r180 top
P1301 "TSM-105-01-T-SV" SMTC-TSM-105-01-X-SV 207.343,32.059 r180 top
Q900 "BSS806NEH6327XTSA1" SOT-23L 23.3,33 r270 bottom value=20V
"R1_Phase A" "CRCW06030000Z0EA" 0603#1 205.919,54.899 r0 top value=0 (schematic designator R1)
"R1_Phase B" "CRCW06030000Z0EA" 0603#1 206.042,70.136 r0 top value=0 (schematic designator R1)
"R1_Phase C" "CRCW06030000Z0EA" 0603#1 205.995,62.599 r0 top value=0 (schematic designator R1)
R2 "RC0603FR-07100RL" 0603#1 207.35,89.778 r180 top value=100
"R3_Phase A" "CRCW06030000Z0EA" 0603#1 205.926,52.365 r0 top value=0 (schematic designator R3)
"R3_Phase B" "CRCW06030000Z0EA" 0603#1 206.042,67.636 r0 top value=0 (schematic designator R3)
"R3_Phase C" "CRCW06030000Z0EA" 0603#1 205.995,59.999 r0 top value=0 (schematic designator R3)
R4 "CRCW060310K0FKEA" 0603#1 142.672,55.361 r90 top value=10.0k
R5 "CRCW060310K0FKEA" 0603#1 141.118,55.36 r270 top value=10.0k
R6 "RC0603FR-07100RL" 0603#1 207.35,88.178 r180 top value=100
R7 "CRCW060347R0FKEA" 0603#1 118.343,43.136 r90 top value=47.0
R8 "CRCW06034K64FKEA" 0603#1 90.614,67.136 r180 top value=4.64k
R9 "CRCW060310R0FKEA" 0603#1 207.443,86.542 r180 bottom value=10.0
R10 "CRCW060310R0FKEA" 0603#1 135.143,59.002 r180 bottom value=10.0
R10jump "5106" 5106#1 144.247,58.649 r270 bottom value=0
R11 "CRCW060347R0FKEA" 0603#1 207.35,88.178 r180 bottom value=47.0
R12 "CRCW060347R0FKEA" 0603#1 205.55,91.378 r180 top value=47.0
R13 "CRCW06030000Z0EA" 0603#1 202.25,91.378 r180 top value=0
R14 "CRCW0603100RFKEA" 0603#1 113.243,37.326 r0 bottom value=100
R15 "CRCW06034K70JNEA" 0603#1 103.843,37.536 r90 bottom value=4.7k
R16 "CRCW06034K70JNEA" 0603#1 103.043,33.736 r180 bottom value=4.7k
R17 "CRCW06031K15FKEA" 0603#1 90.614,68.836 r180 top value=1.15k
R18 "CRCW060347R0FKEA" 0603#1 120.943,42.936 r180 top value=47.0
"R19_Phase A" "ERA3AEB102V" 0603#1 224.95,19.178 r90 top value=1.00k (schematic designator R19)
"R19_Phase B" "ERA3AEB102V" 0603#1 236.95,19.278 r90 top value=1.00k (schematic designator R19)
"R19_Phase C" "ERA3AEB102V" 0603#1 249.45,19.078 r90 top value=1.00k (schematic designator R19)
"R20_Phase A" "CRCW060310R0FKEA" 0603#1 227.75,19.178 r270 top value=10.0 (schematic designator R20)
"R20_Phase B" "CRCW060310R0FKEA" 0603#1 239.843,19.336 r270 top value=10.0 (schematic designator R20)
"R20_Phase C" "CRCW060310R0FKEA" 0603#1 252.743,19.036 r270 top value=10.0 (schematic designator R20)
"R21_Phase A" "ERA3AEB102V" 0603#1 224.95,15.978 r90 top value=1.00k (schematic designator R21)
"R21_Phase B" "ERA3AEB102V" 0603#1 236.95,16.078 r90 top value=1.00k (schematic designator R21)
"R21_Phase C" "ERA3AEB102V" 0603#1 249.45,15.778 r90 top value=1.00k (schematic designator R21)
"R22_Phase A" "CRCW06037K15FKEA" 0603#1 229.45,15.978 r270 top value=7.15k (schematic designator R22)
"R22_Phase B" "CRCW06037K15FKEA" 0603#1 241.45,16.078 r270 top value=7.15k (schematic designator R22)
"R22_Phase C" "CRCW06037K15FKEA" 0603#1 254.35,15.778 r270 top value=7.15k (schematic designator R22)
"R23_Phase A" "CRCW251227R0FKEG" 2512 228.003,12.178 r0 top value=27.0 (schematic designator R23)
"R23_Phase B" "CRCW251227R0FKEG" 2512 240.003,12.178 r0 top value=27.0 (schematic designator R23)
"R23_Phase C" "CRCW251227R0FKEG" 2512 252.343,12.136 r0 top value=27.0 (schematic designator R23)
"R24_Phase A" "ERA-3AEB2492V" 0603#1 226.45,15.978 r90 top value=24.9k (schematic designator R24)
"R24_Phase B" "ERA-3AEB2492V" 0603#1 238.45,16.078 r90 top value=24.9k (schematic designator R24)
"R24_Phase C" "ERA-3AEB2492V" 0603#1 251.15,15.778 r90 top value=24.9k (schematic designator R24)
R25 "CRCW06030000Z0EA" 0603#1 208.05,92.178 r270 top value=0
R26 "CRCW06034K64FKEA" 0603#1 90.614,70.536 r180 top value=4.64k
R27 "CRCW06030000Z0EA" 0603#1 99.043,83.036 r180 top value=0
R28 "CRCW06030000Z0EA" 0603#1 99.043,81.436 r180 top value=0
R29 "CRCW06030000Z0EA" 0603#1 99.043,79.836 r180 top value=0
R30 "CRCW06030000Z0EA" 0603#1 99.043,78.236 r180 top value=0
R31 "CRCW060310K0FKEA" 0603#1 78.343,99.836 r180 top value=10.0k
R32 "CRCW060310K0FKEA" 0603#1 82.793,101.236 r0 bottom value=10.0k
R33 "CRCW060310K0FKEA" 0603#1 82.243,93.836 r90 bottom value=10.0k
R34 "CRCW060310K0FKEA" 0603#1 82.843,91.436 r0 bottom value=10.0k
R35 "CRCW060310K0FKEA" 0603#1 86.243,99.736 r180 bottom value=10.0k
R36 "CRCW060310K0FKEA" 0603#1 75.099,93.736 r270 bottom value=10.0k
R37 "CRCW060310K0FKEA" 0603#1 156.495,90.111 r180 top value=10.0k
R38 "CRCW060310K0FKEA" 0603#1 156.495,82.211 r180 top value=10.0k
R39 "CRCW060310K0FKEA" 0603#1 156.495,75.711 r180 top value=10.0k
R40 "CRCW060310K0FKEA" 0603#1 156.495,85.411 r180 top value=10.0k
R41 "CRCW060310K0FKEA" 0603#1 156.495,79.011 r180 top value=10.0k
R42 "CRCW060310K0FKEA" 0603#1 169.145,79.636 r270 bottom value=10.0k
R43 "CRCW060310K0FKEA" 0603#1 99.043,75.036 r0 top value=10.0k
R44 "CRCW060310K0FKEA" 0603#1 99.043,71.836 r0 top value=10.0k
R45 "CRCW060310K0FKEA" 0603#1 99.043,68.636 r0 top value=10.0k
R46 "CRCW060310K0FKEA" 0603#1 99.043,76.636 r0 top value=10.0k
R47 "CRCW060310K0FKEA" 0603#1 99.043,73.436 r0 top value=10.0k
R48 "CRCW060310K0FKEA" 0603#1 99.043,70.236 r0 top value=10.0k
R49 "CRCW060310K0FKEA" 0603#1 156.495,88.511 r0 top value=10.0k
R50 "CRCW060310K0FKEA" 0603#1 156.495,83.811 r0 top value=10.0k
R51 "CRCW060310K0FKEA" 0603#1 156.495,77.311 r0 top value=10.0k
R52 "CRCW060310K0FKEA" 0603#1 156.495,86.911 r0 top value=10.0k
R53 "CRCW060310K0FKEA" 0603#1 156.495,80.611 r0 top value=10.0k
R54 "CRCW060310K0FKEA" 0603#1 170.642,79.636 r90 bottom value=10.0k
R55 "CRCW060310K0FKEA" 0603#1 91.943,93.836 r90 bottom value=10.0k
R56 "CRCW060310K0FKEA" 0603#1 76.343,89.736 r0 bottom value=10.0k
R57 "CRCW060310K0FKEA" 0603#1 90.221,93.802 r270 bottom value=10.0k
R58 "CRCW060310K0FKEA" 0603#1 70.643,95.336 r90 top value=10.0k
R59 "CRCW06034K70JNEA" 0603#1 148.442,48.898 r0 bottom value=4.7k
R100 "CRCW06031M00FKEA" 0603#2 5.9,48.1 r135 bottom value=1.00Meg
R101 "CRCW06031M00FKEA" 0603#2 5.9,81.5 r135 bottom value=1.00Meg
R102 "CRCW06031M00FKEA" 0603#2 263.9,52.7 r315 bottom value=1.00Meg
R103 "5106" 5106#1 146.343,55.436 r0 bottom value=0
R104 "5106" 5106#1 142.743,55.036 r0 bottom value=0
R105 "5106" 5106#1 248.743,46.036 r0 top value=0
R106 "5106" 5106#1 248.743,48.236 r0 top value=0
R113 "5106" 5106#1 204.843,22.536 r90 bottom value=0
R114 "5106" 5106#1 65.543,36.136 r180 top value=0
R115 "5106" 5106#1 201.443,23.836 r0 bottom value=0
R116 "5106" 5106#1 53.25,22.878 r90 top value=0
R235 "CRCW0603100KFKEA" 0603#2 28.15,12.363 r180 bottom value=100k
R236 "CRCW060378K7FKEA" 0603#2 28.257,6.863 r180 bottom value=78.7k
R237 "CRCW060315K0FKEA" 0603#2 28.2,4.563 r180 bottom value=15.0k
R238 "CRCW06035K11FKEA" 0603#2 31.357,6.863 r180 bottom value=5.11k
R239 "CRCW06035K36FKEA" 0603#2 31.3,14.749 r180 bottom value=5.36k
R240 "CRCW060320K0FKEA" 0603#2 31.3,12.363 r180 bottom value=20.0k
R241 "CRCW06033K01FKEA" 0603#2 31.3,4.563 r180 bottom value=3.01k
R242 "CRCW121010R0FKEAHP" 1210 50.6,56.55 r0 bottom value=10.0
R243 "CRCW060334K8FKEA" 0603#2 37.1,50.286 r0 bottom value=34.8k
R244 "CRCW06035K23FKEA" 0603#2 46.8,60.45 r90 bottom value=5.23k
R245 "CRCW060324K9FKEA" 0603#2 39.443,51.086 r270 bottom value=24.9k
R246 "CRCW0603121KFKEA" 0603#2 44,60.45 r270 bottom value=121k
R247 "CRCW060322K6FKEA" 0603#2 37.1,53.75 r0 bottom value=22.6k
R248 "CRCW06035K49FKEA" 0603#2 39.443,58.586 r270 bottom value=5.49k
R249 "CRCW060349K9FKEA" 0603#2 37.1,52.35 r0 bottom value=49.9k
R250 "CRCW060361K9FKEA" 0603#2 42.243,58.586 r270 bottom value=61.9k
R251 "CRCW06032K00FKEA" 0603#2 36.843,57.686 r0 bottom value=2.00k
R300 "CRCW0603100KFKEA" 0603#2 35.257,12.443 r180 bottom value=100k
R301 "CRCW060378K7FKEA" 0603#2 35.257,6.843 r180 bottom value=78.7k
R302 "CRCW060315K0FKEA" 0603#2 35.268,4.443 r180 bottom value=15.0k
R303 "CRCW06035K11FKEA" 0603#2 38.457,6.843 r180 bottom value=5.11k
R304 "CRCW06035K36FKEA" 0603#2 38.357,14.743 r180 bottom value=5.36k
R305 "CRCW060320K0FKEA" 0603#2 38.357,12.443 r180 bottom value=20.0k
R306 "CRCW06035K11FKEA" 0603#2 38.368,4.443 r180 bottom value=5.11k
R307 "CRCW060340K2FKEA" 0603#2 33,25.5 r90 bottom value=40.2k
R308 "CRCW060310K0FKEA" 0603#2 34.4,25.5 r270 bottom value=10.0k
R309 "CRCW121010R0FKEAHP" 1210 50.6,40.15 r0 bottom value=10.0
R310 "CRCW060334K8FKEA" 0603#2 37.1,33.886 r0 bottom value=34.8k
R311 "CRCW06035K23FKEA" 0603#2 46.8,43.95 r90 bottom value=5.23k
R312 "CRCW060324K9FKEA" 0603#2 39.443,34.686 r270 bottom value=24.9k
R313 "CRCW0603121KFKEA" 0603#2 44,43.95 r270 bottom value=121k
R314 "CRCW060322K6FKEA" 0603#2 37.1,37.35 r0 bottom value=22.6k
R315 "CRCW06035K49FKEA" 0603#2 39.443,42.186 r270 bottom value=5.49k
R316 "CRCW060349K9FKEA" 0603#2 37.1,35.95 r0 bottom value=49.9k
R317 "CRCW060361K9FKEA" 0603#2 42.243,42.186 r270 bottom value=61.9k
R318 "CRCW06032K00FKEA" 0603#2 36.843,41.286 r0 bottom value=2.00k
R319 "CRCW060310K0FKEA" 0603#1 37.2,22.4 r90 bottom value=10.0k
R320 "CRCW060310K0FKEA" 0603#1 38.6,25.5 r270 bottom value=10.0k
R321 "CRCW06037K15FKEA" 0603#1 40,25.5 r270 bottom value=7.15k
R322 "CRCW060310K0FKEA" 0603#1 37.2,25.5 r270 bottom value=10.0k
R324 "5106" 5106#1 63.443,30.536 r270 top value=0
R325 "5106" 5106#1 62.1,22.9 r90 bottom value=0
R400 "CRCW0603100KFKEA" 0603#2 42.3,12.643 r180 bottom value=100k
R402 "CRCW060378K7FKEA" 0603#2 42.3,6.843 r180 bottom value=78.7k
R405 "CRCW060315K0FKEA" 0603#2 42.3,4.543 r180 bottom value=15.0k
R406 "CRCW06035K11FKEA" 0603#2 45.4,6.843 r180 bottom value=5.11k
R410 "CRCW06035K36FKEA" 0603#2 45.4,15.143 r180 bottom value=5.36k
R416 "CRCW060320K0FKEA" 0603#2 45.4,12.643 r180 bottom value=20.0k
R417 "CRCW06035K11FKEA" 0603#2 45.4,4.543 r180 bottom value=5.11k
R421 "CRCW121010R0FKEAHP" 1210 82.1,48.6 r0 bottom value=10.0
R425 "CRCW060334K8FKEA" 0603#2 68.8,41.736 r0 bottom value=34.8k
R426 "CRCW06035K36FKEA" 0603#2 78.3,51.1 r90 bottom value=5.36k
R427 "CRCW121010R0FKEAHP" 1210 82.1,44 r0 bottom value=10.0
R428 "CRCW060322K6FKEA" 0603#2 68.8,45.2 r0 bottom value=22.6k
R429 "CRCW060324K9FKEA" 0603#2 71.143,42.536 r270 bottom value=24.9k
R430 "CRCW060371K5FKEA" 0603#2 75.5,51.1 r270 bottom value=71.5k
R431 "CRCW06035K49FKEA" 0603#2 71.143,50.036 r270 bottom value=5.49k
R432 "CRCW060349K9FKEA" 0603#2 68.8,43.8 r0 bottom value=49.9k
R433 "CRCW060361K9FKEA" 0603#2 73.943,50.036 r270 bottom value=61.9k
R434 "CRCW06032K00FKEA" 0603#2 68.543,49.136 r0 bottom value=2.00k
R500 "CRCW06036K04FKEA" 0603#2 60.238,66.911 r180 top value=6.04k
R501 "CRCW06032K00FKEA" 0603#2 67.838,66.911 r180 top value=2.00k
R502 "CRCW06032K00FKEA" 0603#2 60.238,68.311 r180 top value=2.00k
R503 "CRCW06030000Z0EA" 0603#2 16.766,37.614 r135 top value=0
R504 "CRCW06030000Z0EA" 0603#2 14.4,39.98 r135 top value=0
R505 "CRCW060310K0FKEA" 0603#2 63.544,68.286 r0 top value=10.0k
R506 "CRCW060310K0FKEA" 0603#2 63.544,71.086 r180 top value=10.0k
R507 "CRCW060310K0FKEA" 0603#2 67.843,74.036 r0 top value=10.0k
R508 "CRCW060310K0FKEA" 0603#2 63.544,73.886 r180 top value=10.0k
R509 "CRCW060310K0FKEA" 0603#2 63.544,72.486 r180 top value=10.0k
R510 "CRCW060310K0FKEA" 0603#2 65.638,77.911 r90 top value=10.0k
R511 "CRCW060368K1FKEA" 0603#2 67.038,77.911 r270 top value=68.1k
R512 "CRCW060368K1FKEA" 0603#2 68.438,77.911 r270 top value=68.1k
R513 "CRCW06030000Z0EA" 0603#2 122.944,55.487 r180 bottom value=0
R514 "CRCW060347R0FKEA" 0603#2 119.643,56.936 r0 bottom value=47.0
R515 "CRCW060320K0FKEA" 0603#2 49.738,77.911 r270 top value=20.0k
R516 "CRCW060310K0FKEA" 0603#2 69.838,77.911 r90 top value=10.0k
R517 "CRCW060310K0FKEA" 0603#2 62.638,77.911 r90 top value=10.0k
R518 "CRCW060334K8FKEA" 0603#2 60.238,77.111 r180 top value=34.8k
R519 "CRCW06031K00FKEA" 0603#2 55.438,78.711 r180 top value=1.00k
R520 "CRCW0603100RFKEA" 0603#2 52.138,77.111 r180 top value=100
R521 "CRCW06030000Z0EA" 0603#2 14.4,31.9 r135 top value=0
R522 "CRCW060340K2FKEA" 0603#2 51.338,79.511 r270 top value=40.2k
R523 "CRCW060334K8FKEA" 0603#2 60.238,78.711 r180 top value=34.8k
R524 "CRCW06031K00FKEA" 0603#2 55.438,80.311 r180 top value=1.00k
R525 "CRCW0603100RFKEA" 0603#2 52.138,81.911 r180 top value=100
R526 "CRCW06030000Z0EA" 0603#2 16.766,29.534 r135 top value=0
R527 "CRCW06030000Z0EA" 0603#2 73.943,71.536 r90 top value=0
R528 "CRCW060347R0FKEA" 0603#2 123.458,39.258 r0 bottom value=47.0
R529 "CRCW060310K0FKEA" 0603#2 64.238,77.911 r90 top value=10.0k
R530 "CRCW060320K0FKEA" 0603#2 49.738,81.111 r270 top value=20.0k
R533 "CRCW060320K0FKEA" 0603#2 49.738,85.511 r270 top value=20.0k
R534 "CRCW060310K0FKEA" 0603#2 62.638,88.711 r90 top value=10.0k
R535 "CRCW060334K8FKEA" 0603#2 60.238,87.911 r180 top value=34.8k
R536 "CRCW06031K00FKEA" 0603#2 55.438,86.311 r180 top value=1.00k
R537 "CRCW0603100RFKEA" 0603#2 52.138,84.711 r180 top value=100
R538 "CRCW06030000Z0EA" 0603#2 14.4,35.94 r135 top value=0
R539 "5106" 5106#2 71.738,82.061 r90 top value=0
R540 "CRCW060340K2FKEA" 0603#2 51.338,87.111 r270 top value=40.2k
R541 "5106" 5106#2 71.738,85.311 r270 top value=0
R542 "CRCW060334K8FKEA" 0603#2 60.238,89.511 r180 top value=34.8k
R543 "CRCW06031K00FKEA" 0603#2 55.438,87.911 r180 top value=1.00k
R544 "CRCW0603100RFKEA" 0603#2 52.138,89.511 r180 top value=100
R545 "CRCW06030000Z0EA" 0603#2 16.766,33.574 r135 top value=0
R546 "CRCW06030000Z0EA" 0603#2 72.375,71.557 r90 top value=0
R547 "CRCW060347R0FKEA" 0603#2 123.418,34.942 r0 bottom value=47.0
R548 "CRCW060310K0FKEA" 0603#2 64.238,88.711 r270 top value=10.0k
R549 "CRCW060320K0FKEA" 0603#2 49.738,88.711 r270 top value=20.0k
R550 "CRCW06030000Z0EA" 0603#2 67.838,71.111 r180 top value=0
R551 "CRCW06030000Z0EA" 0603#2 67.838,72.511 r180 top value=0
R552 "CRCW060310K0FKEA" 0603#1 85.65,78.753 r0 top value=10.0k
R553 "CRCW060310K0FKEA" 0603#1 78.65,78.753 r0 top value=10.0k
R554 "CRCW060310K0FKEA" 0603#1 85.65,77.353 r180 top value=10.0k
R555 "CRCW060310K0FKEA" 0603#1 78.65,77.353 r180 top value=10.0k
R556 "CRCW06036K04FKEA" 0603#1 87.25,74.453 r180 top value=6.04k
